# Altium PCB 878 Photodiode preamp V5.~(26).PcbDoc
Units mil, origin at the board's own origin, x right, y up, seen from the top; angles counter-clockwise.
Board outline 4488 x 4488 mil, 6 copper layers (Top Layer, Internal Plane 1, Dummy Ground, Dummy Power, Internal Plane 2, Bottom Layer), stack 21.034 mil thick; 182 components, 80 nets, 485 pads, 76 vias.
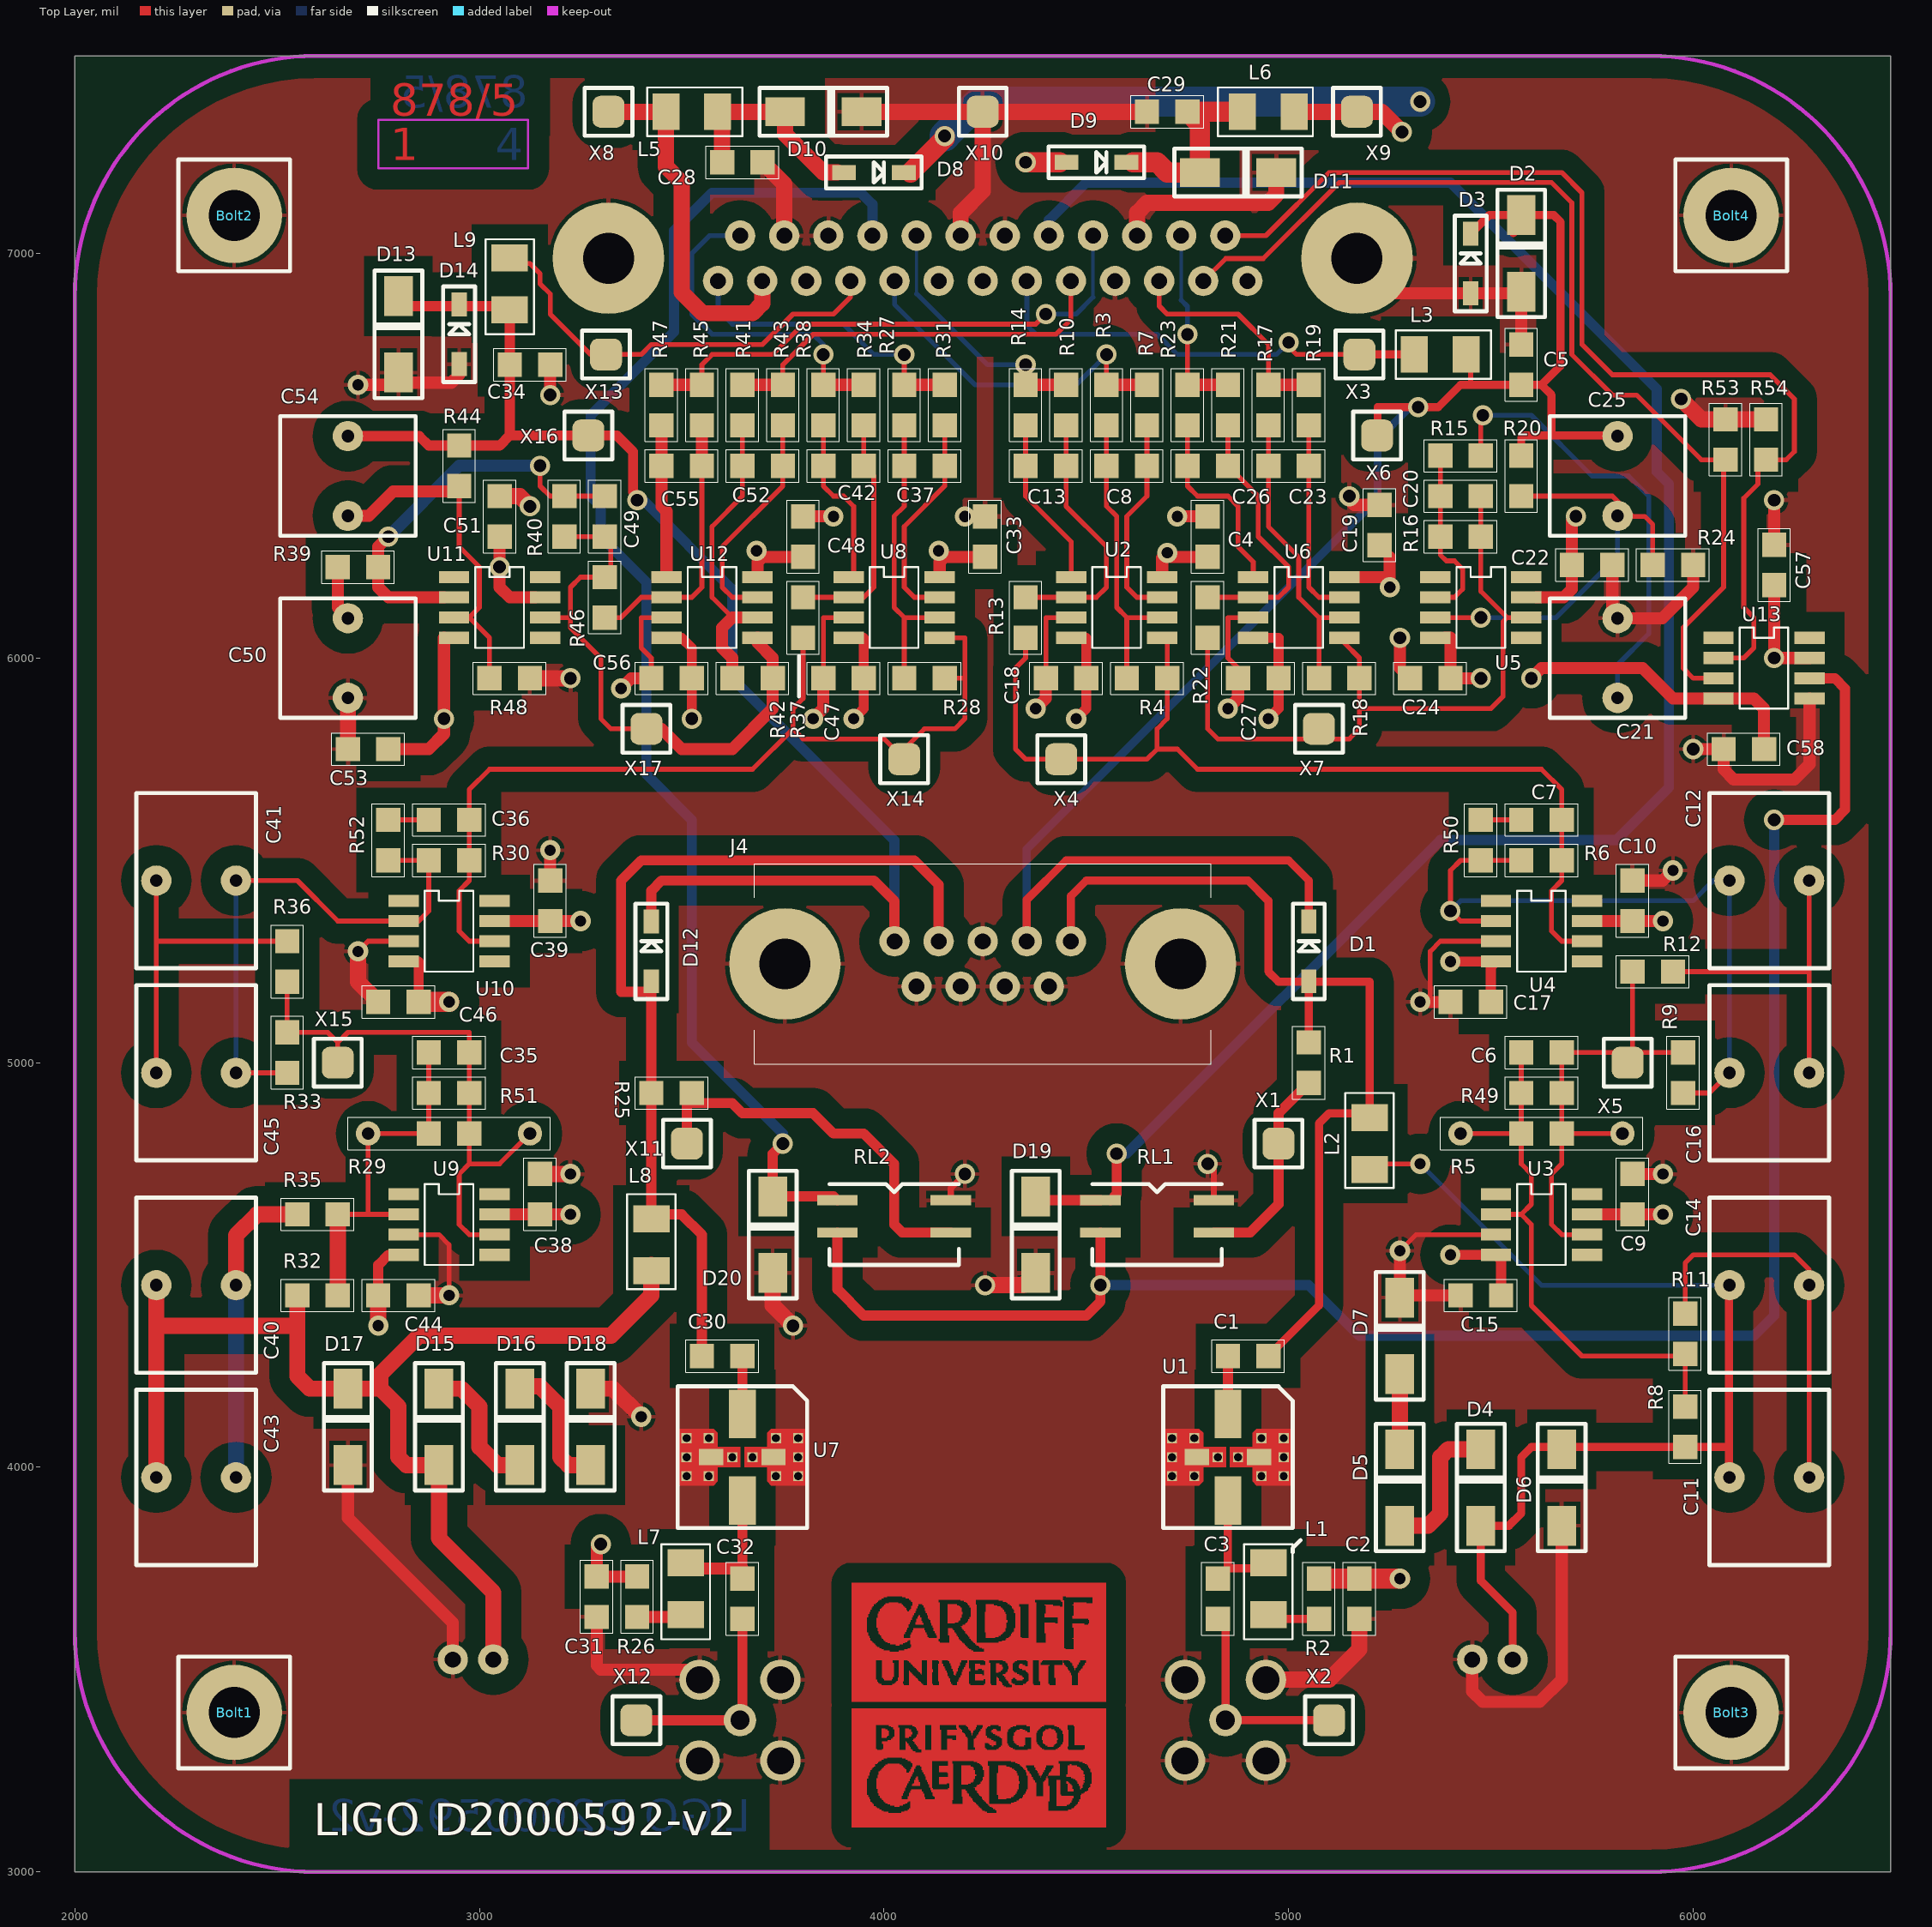
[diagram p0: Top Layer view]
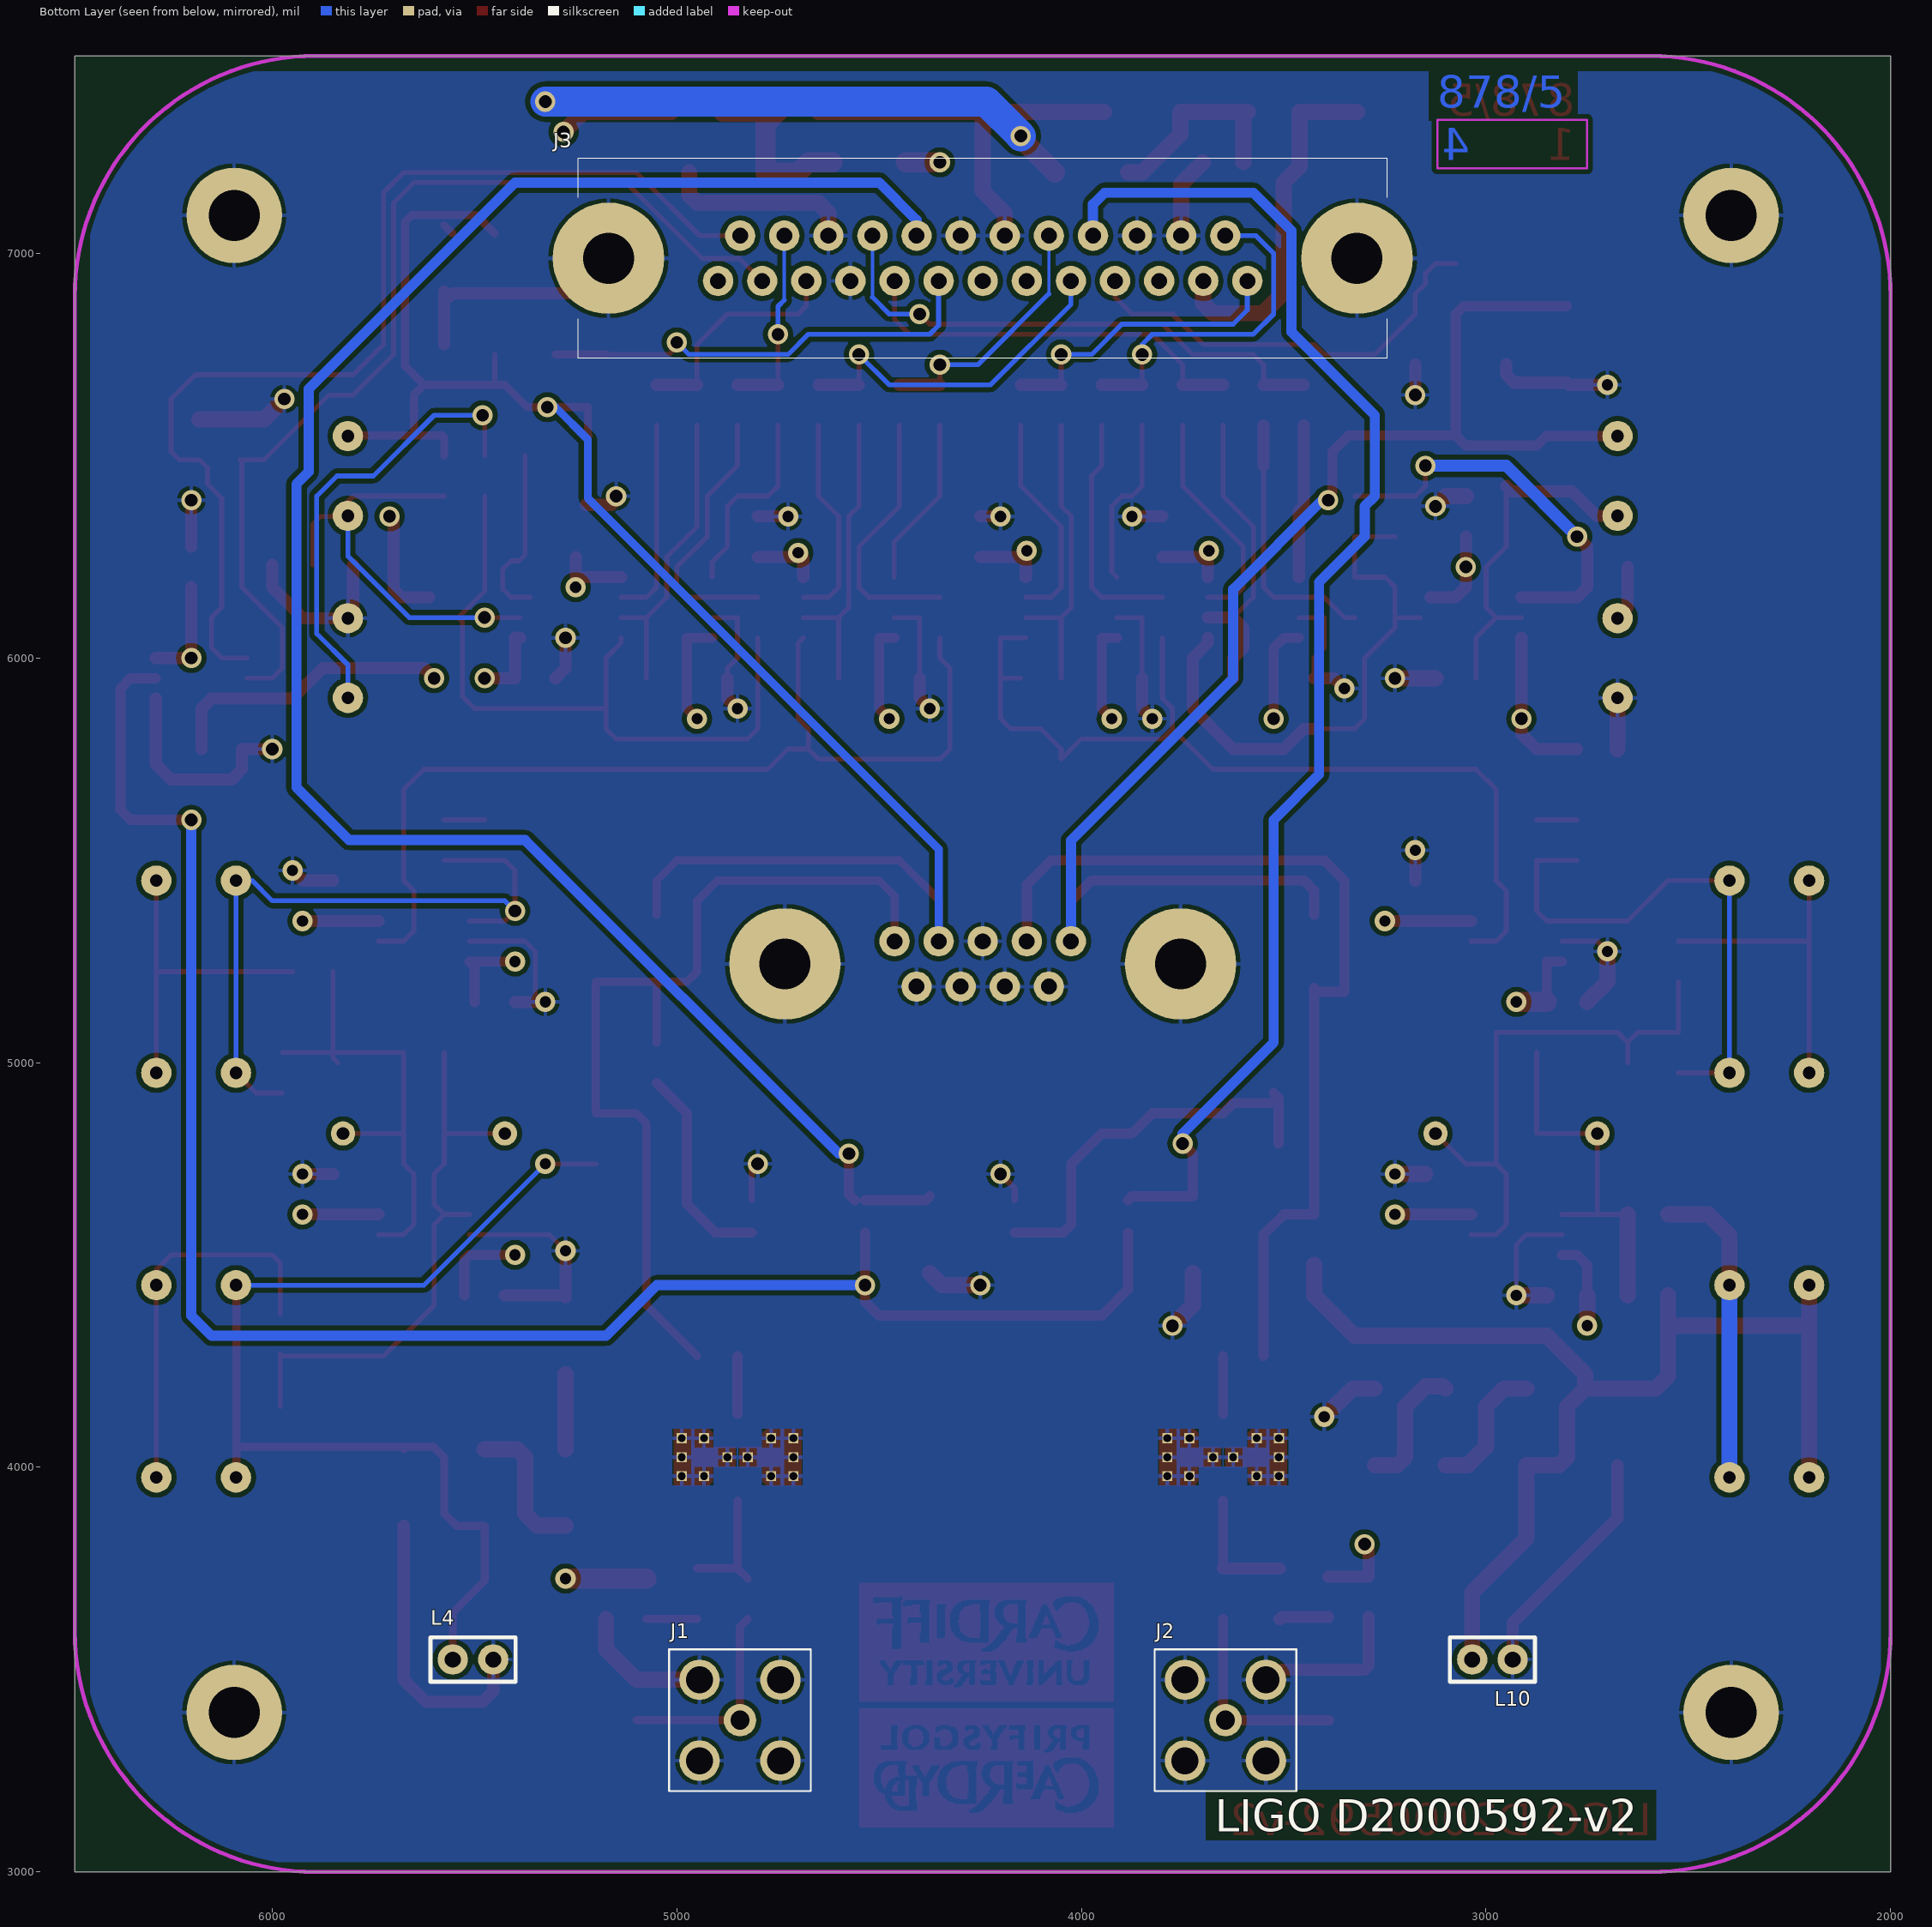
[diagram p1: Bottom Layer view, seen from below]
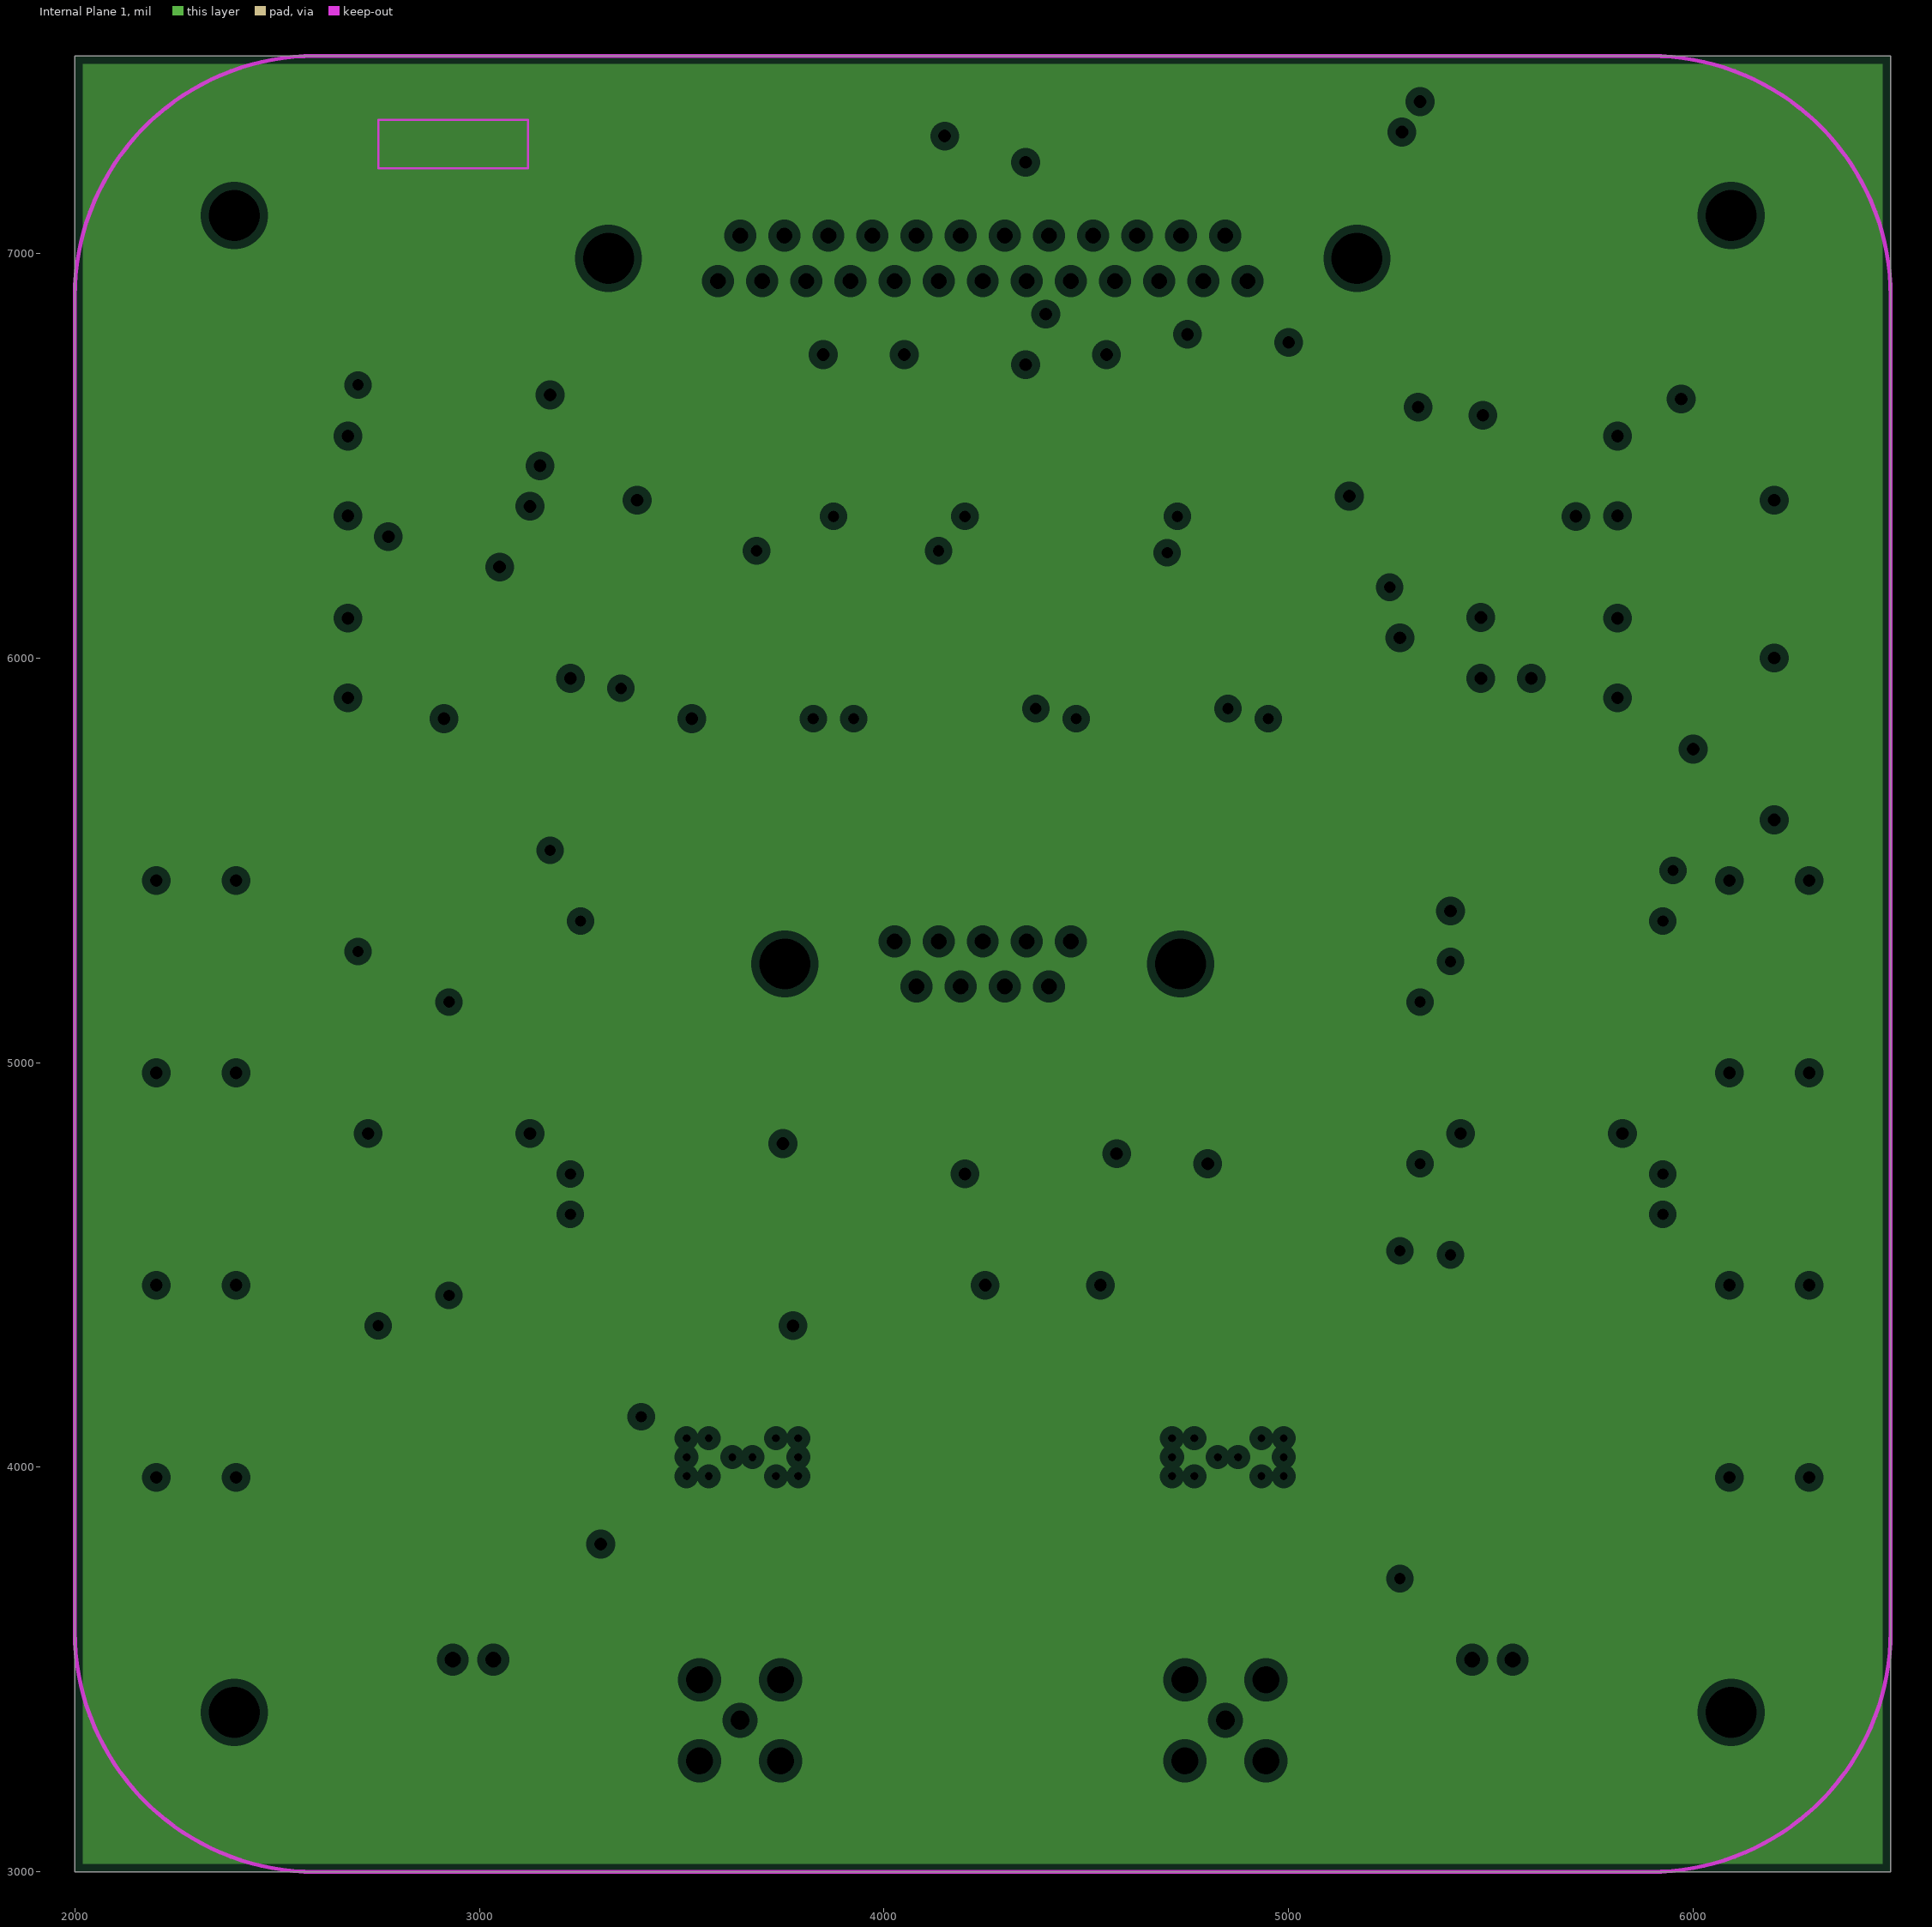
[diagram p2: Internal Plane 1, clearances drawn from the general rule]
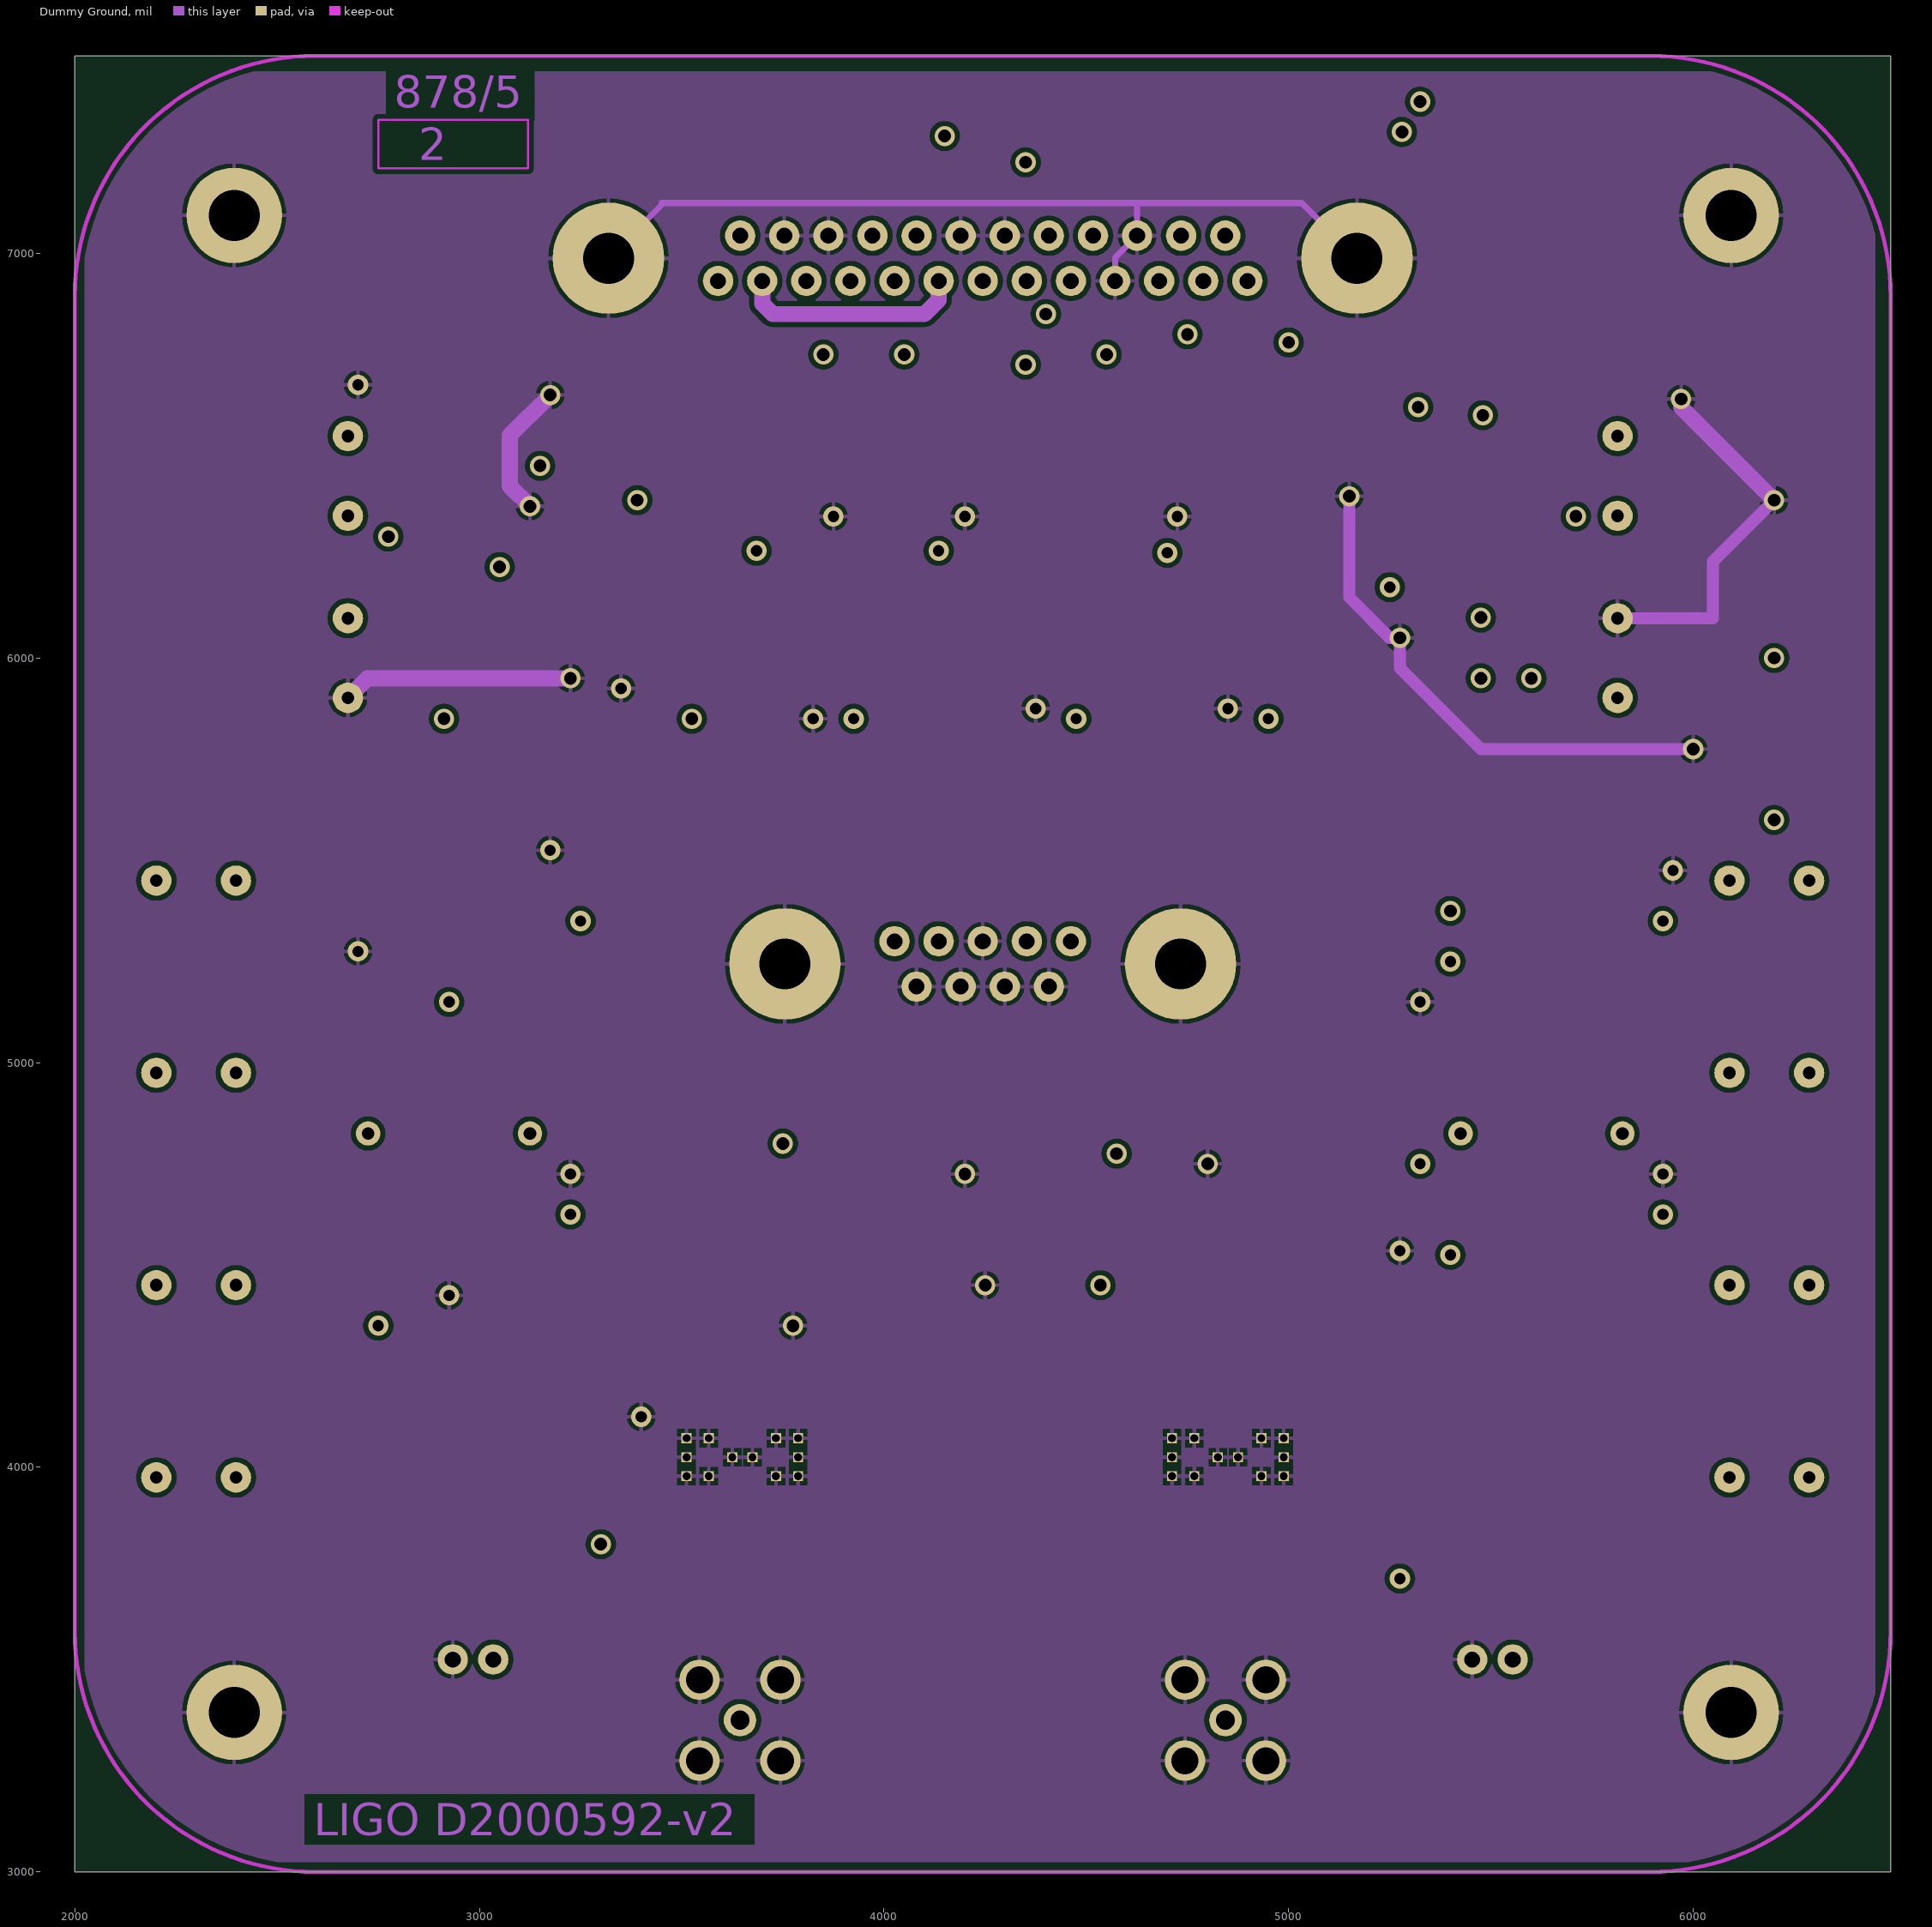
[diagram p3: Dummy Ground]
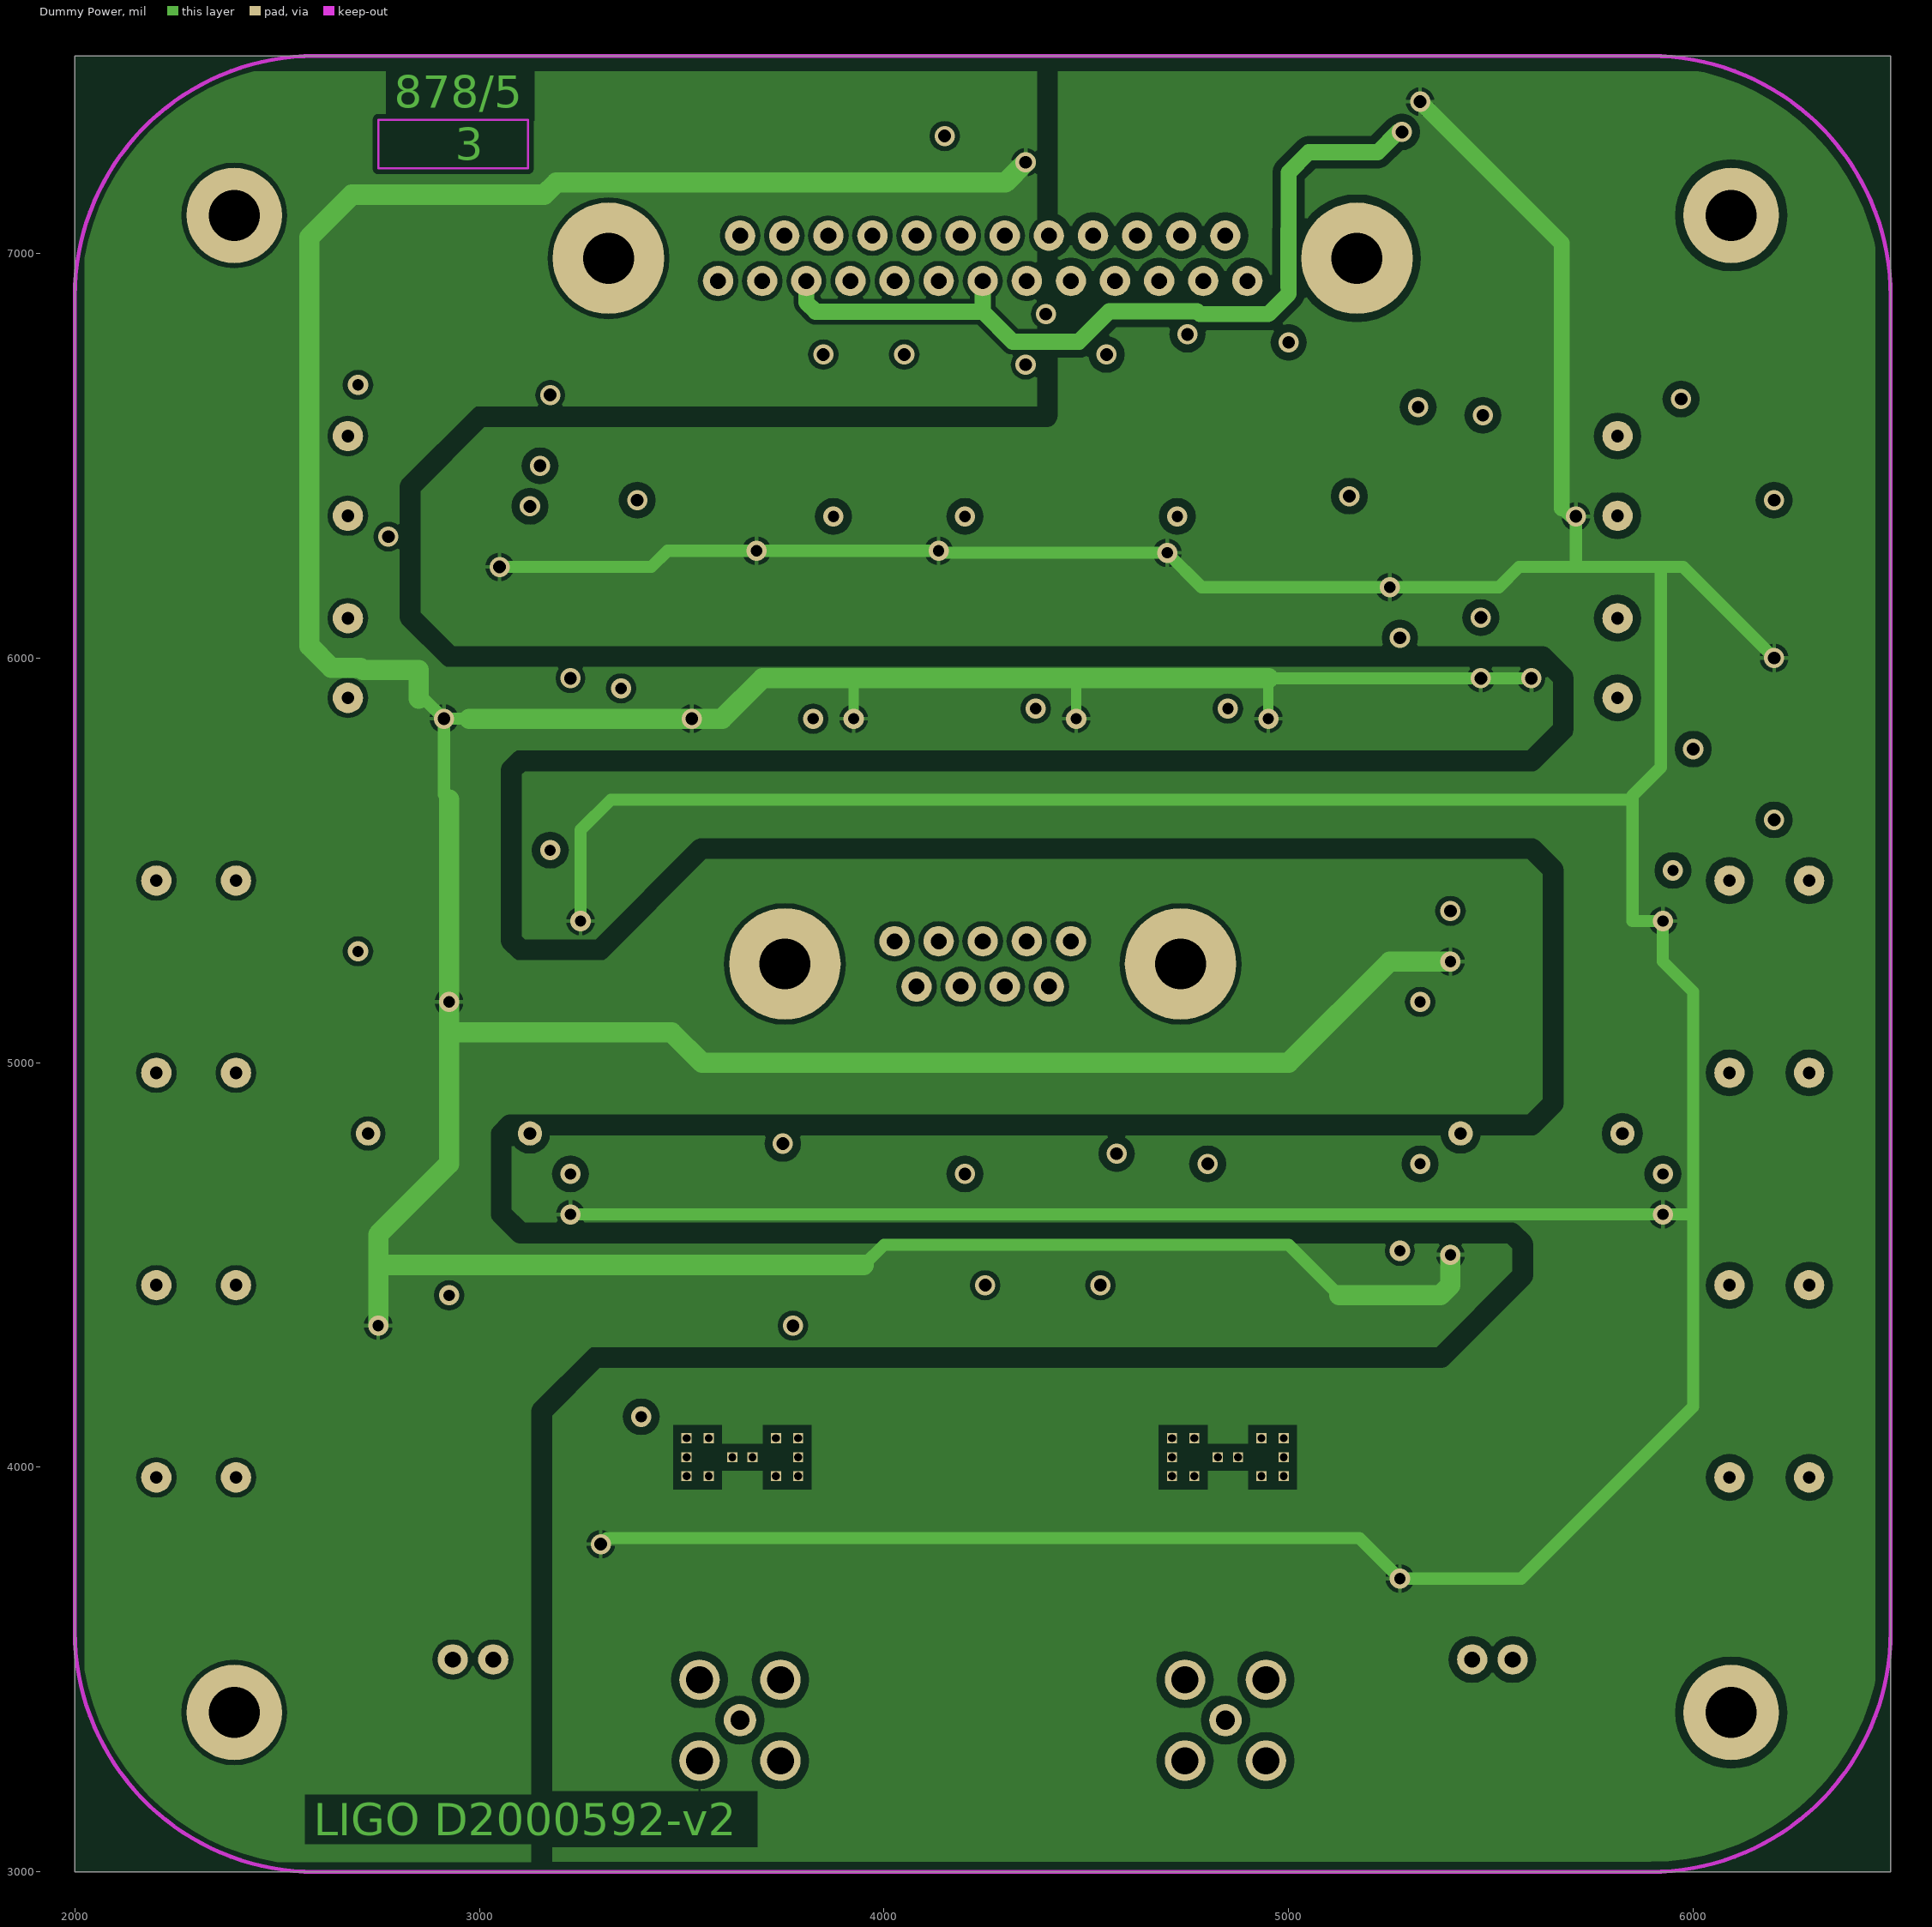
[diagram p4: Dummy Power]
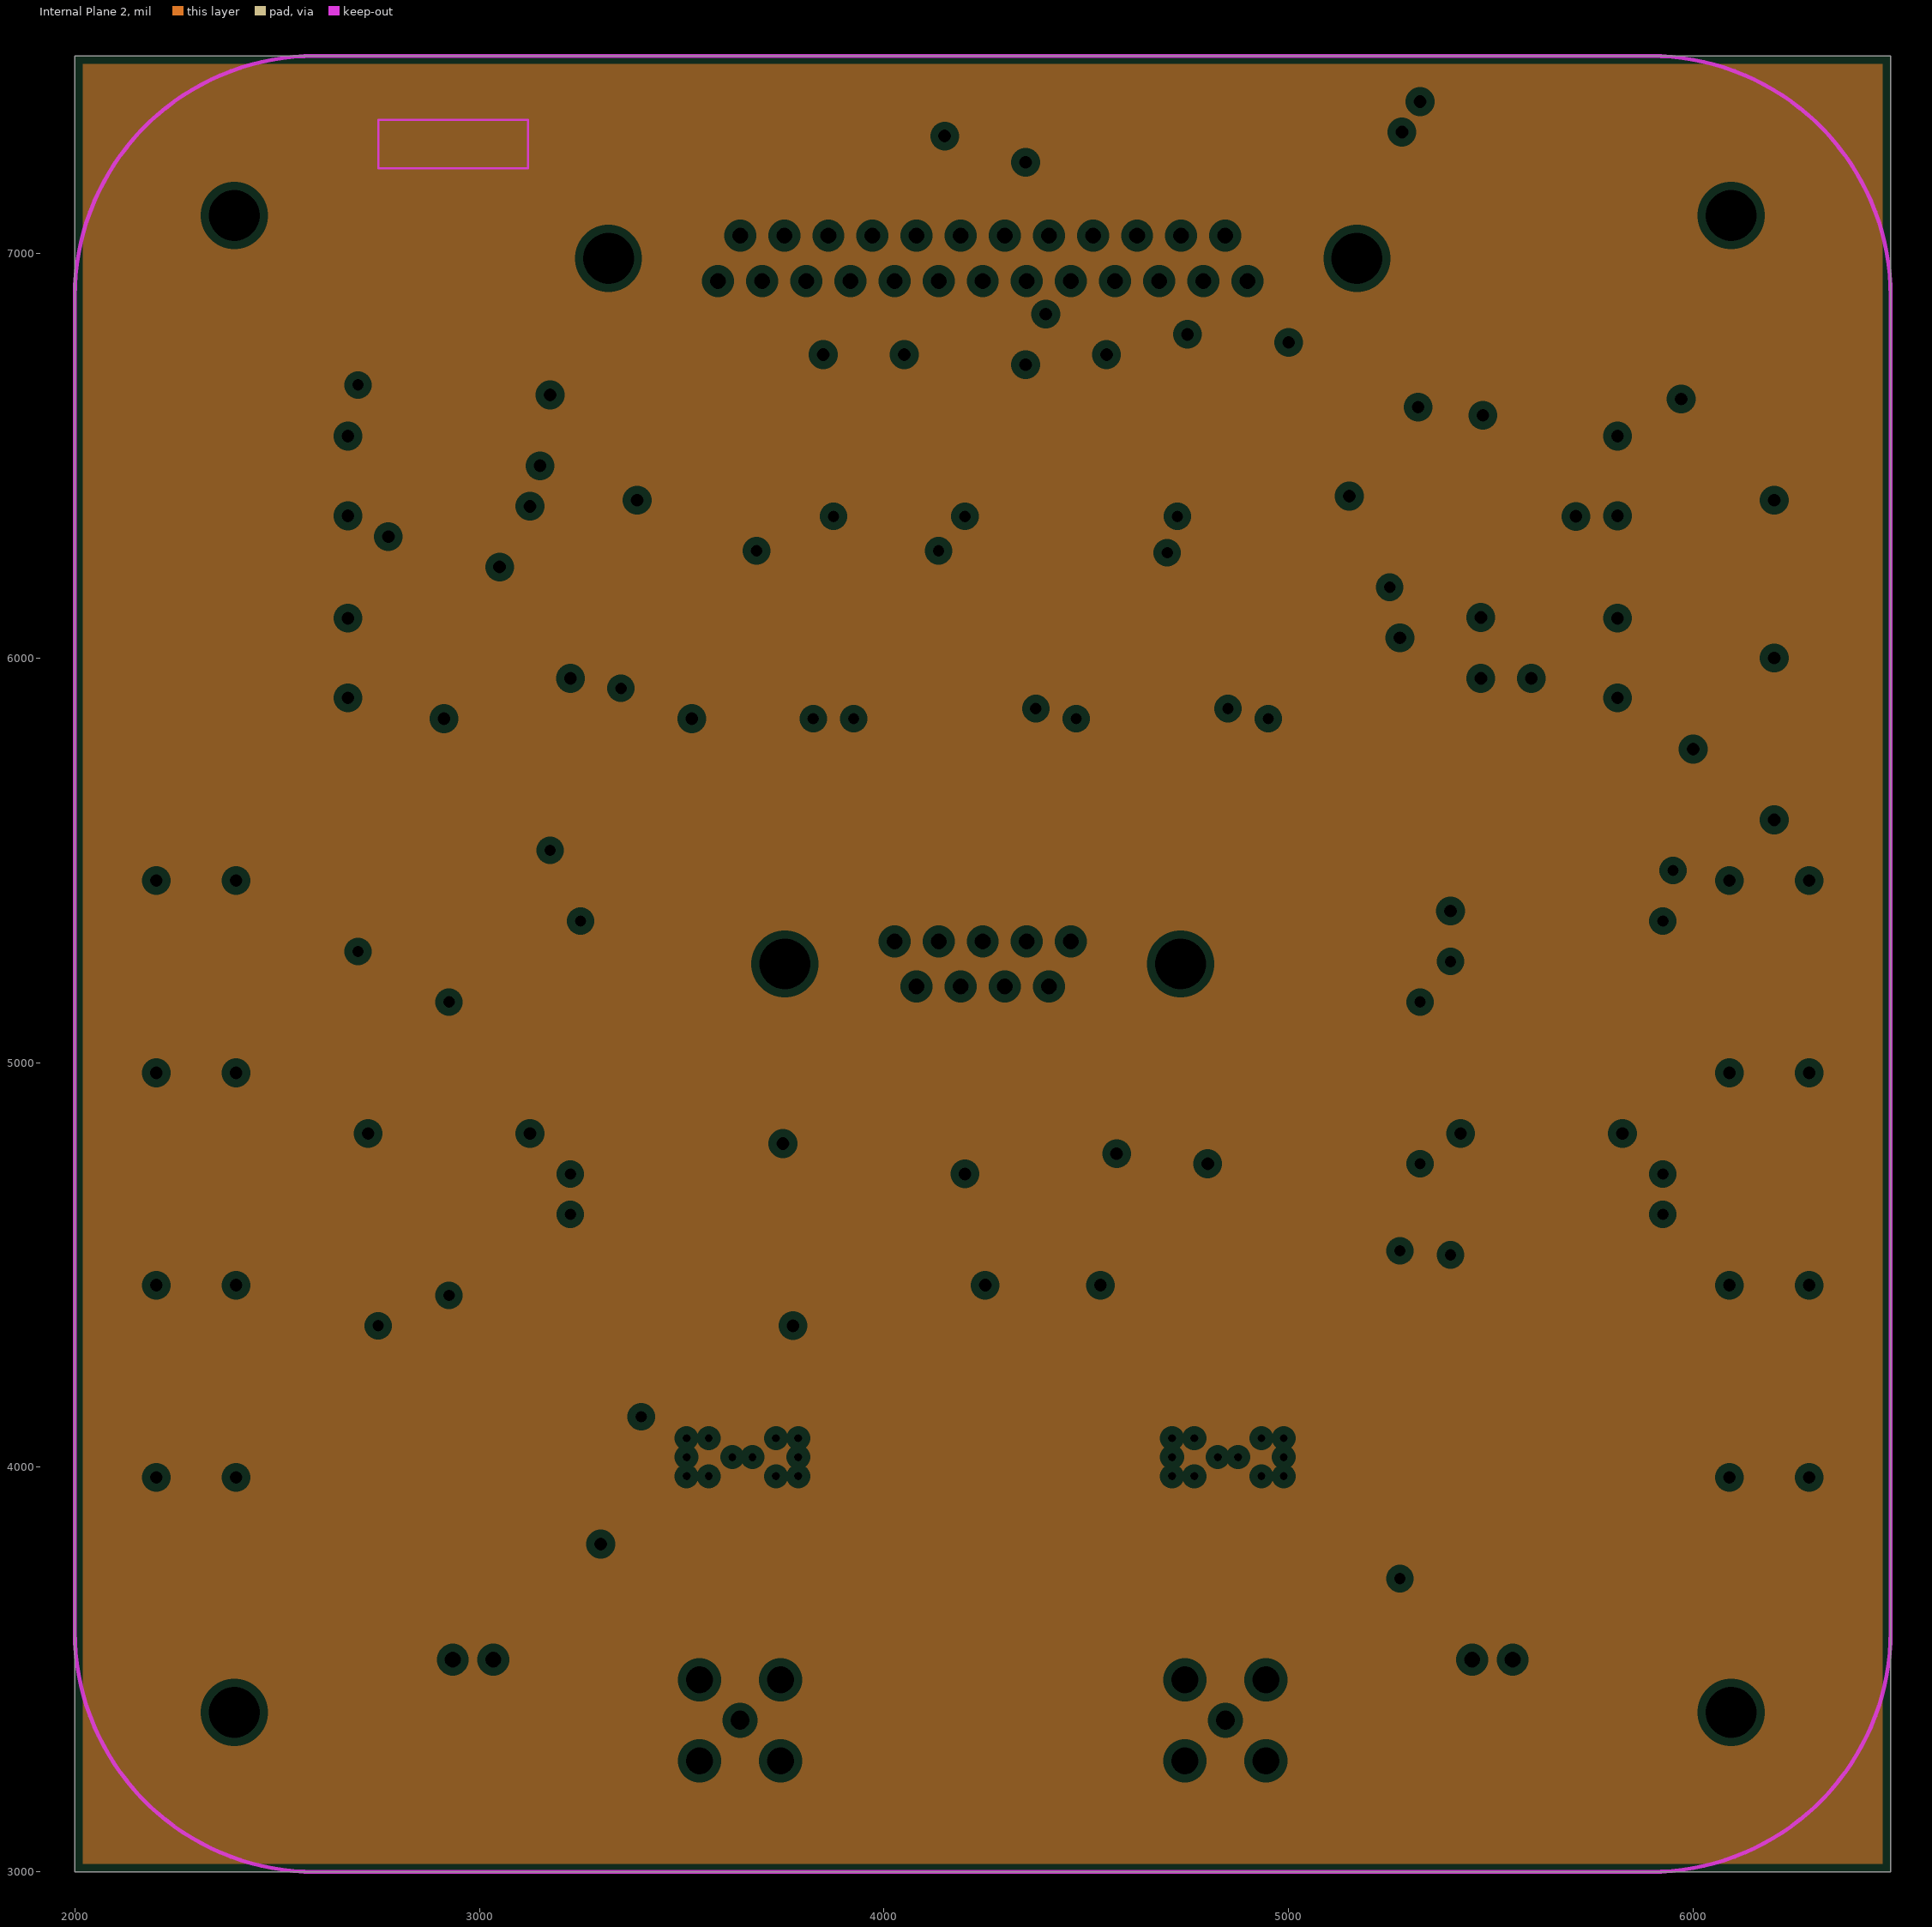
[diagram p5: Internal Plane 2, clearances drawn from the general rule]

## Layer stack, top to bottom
Top Solder: solder mask 0.4, Solder Resist, Dk 3.5
Top Layer: signal copper 1.4
Internal Plane 1: plane copper 1.4
Dummy Ground: signal copper 1.417
Dummy Power: signal copper 1.417
Internal Plane 2: plane copper 1.4
Dielectric 1: dielectric 12.6, FR-4, Dk 4.8
Bottom Layer: signal copper 1.4
Bottom Solder: solder mask 0.4, Solder Resist, Dk 3.5

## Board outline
2000,3000 6488,3000 6488,7488 2000,7488

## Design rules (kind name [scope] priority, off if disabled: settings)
Clearance Clearance_2 [InNamedPolygon('Top Layer-GND')] p1: gap=50
Clearance Clearance_1 [(InNamedPolygon('+15V_L04_P006'))] p2: gap=20
Clearance [All] p3: gap=12
HoleSize [All] p1: absolutevalues=TRUE maxlimit=150 minlimit=1 maxpercent=80.000 minpercent=20.000
PlaneClearance [All] p1: clearance=20
PlaneConnect [All] p1: planeconnectstyle=Relief reliefexpansion=20 reliefentries=4 reliefconductorwidth=10 reliefairgap=10
PolygonConnect [All] p1: connectstyle=Relief reliefconductorwidth=10 reliefentries=4 polygonreliefangle="90 Angle" airgapwidth=10
RoutingVias [All] p1: holewidth=31.5 width=50 viastyle="Through Hole" minholewidth=19.68 minwidth=30 maxholewidth=31.5 maxwidth=60
SilkToSilkClearance [All] p1: silktosilkclearance=5
SilkToSolderMaskClearance [IsPad] p1: minsilkscreentomaskgap=3 clearancetoexposedcopper=TRUE
SolderMaskExpansion [All] p1: expansion=4
Width [All] p1: maxlimit=200 minlimit=8 preferedwidth=12
25 further rules are at their usual default settings.

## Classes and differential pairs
component class "878 Photodiode preamp v5 P1": Bolt1 Bolt2 Bolt3 Bolt4 C1 C2 C3 C4 C5 C6 C7 C8 C9 C10 C11 C12 C13 C14 C15 C16 C17 C18 C19 C20 C21 C22 C23 C24 C25 C26 C27 C28 C29 C57 C58 D1 D2 D3 D4 D5 D6 D7 D8 D9 D10 D11 D19 J1 L1 L2 L3 L4 L5 L6 R1 R2 R3 R4 R5 R6 R7 R8 R9 R10 R11 R12 R13 R14 R15 R16 R17 R18 R19 R20 R21 R22 R23 R24 R49 R50 R53 R54 RL1 U1 U2 U3 U4 U5 U6 U13 X1 X2 X3 X4 X5 X6 X7 X8 X9 X10
component class "878 Photodiode preamp v5 P2": C30 C31 C32 C33 C34 C35 C36 C37 C38 C39 C40 C41 C42 C43 C44 C45 C46 C47 C48 C49 C50 C51 C52 C53 C54 C55 C56 D12 D13 D14 D15 D16 D17 D18 D20 J2 J3 J4 L7 L8 L9 L10 R25 R26 R27 R28 R29 R30 R31 R32 R33 R34 R35 R36 R37 R38 R39 R40 R41 R42 R43 R44 R45 R46 R47 R48 R51 R52 RL2 U7 U8 U9 U10 U11 U12 X11 X12 X13 X14 X15 X16 X17

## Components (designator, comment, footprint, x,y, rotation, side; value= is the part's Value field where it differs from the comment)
Bolt1 "Bolt M3" BOLT 2394,3394 r0 top
Bolt2 "Bolt M3" BOLT 2394,7094 r0 top
Bolt3 "Bolt M3" BOLT 6094,3394 r0 top
Bolt4 "Bolt M3" BOLT 6094,7094 r0 top
C1 "Cap200" HS0805Long 4900,4275 r180 top
C2 "Cap200" HS0805Long 5175,3675 r270 top
C3 "Cap200" HS0805Long 4825,3675 r270 top
C4 "Cap200" HS0805Long 4800,6300 r90 top
C5 "Cap200" HS0805Long 5575,6725 r90 top
C6 "Cap200" HS0805Long 5625,5025 r0 top
C7 "Cap200" HS0805Long 5625,5600 r0 top
C8 "Cap200" HS0805Long 4600,6475 r0 top
C9 "Cap200" HS0805Long 5850,4675 r90 top
C10 "Cap200" HS0805Long 5850,5400 r90 top
C11 "Cap200" "MKS2 7.2 11" 6188,3975 r0 top
C12 "Cap200" "MKS2 7.2 11" 6188,5450 r180 top
C13 "Cap200" HS0805Long 4400,6475 r180 top
C14 "Cap200" "MKS2 7.2 11" 6188,4450 r0 top
C15 "Cap200" HS0805Long 5475,4425 r180 top
C16 "Cap200" "MKS2 7.2 11" 6188,4975 r180 top
C17 "Cap200" HS0805Long 5450,5150 r180 top
C18 "Cap200" HS0805Long 4450,5950 r180 top
C19 "Cap200" HS0805Long 5225,6328.51 r90 top
C20 "Cap200" HS0805Long 5425,6400 r0 top
C21 "Cap200" "MKS2 7.2 8.5" 5813,6000 r270 top
C22 "Cap200" HS0805Long 5750,6230 r0 top
C23 "Cap200" HS0805Long 5000,6475 r0 top
C24 "Cap200" HS0805Long 5350,5950 r180 top
C25 "Cap200" "MKS2 7.2 8.5" 5813,6450 r270 top
C26 "Cap200" HS0805Long 4800,6475 r180 top
C27 "Cap200" HS0805Long 4925,5950 r180 top
C28 "Cap200" HS0805Long 3650,7225 r0 top
C29 "Cap200" HS0805Long 4700,7350 r180 top
C30 "Cap200" HS0805Long 3600,4275 r0 top
C31 "Cap200" HS0805Long 3290,3680 r270 top
C32 "Cap200" HS0805Long 3650,3675 r270 top
C33 "Cap200" HS0805Long 4250,6300 r90 top
C34 "Cap200" HS0805Long 3125,6725 r0 top
C35 "Cap200" HS0805Long 2925,5025 r0 top
C36 "Cap200" HS0805Long 2925,5600 r0 top
C37 "Cap200" HS0805Long 4100,6475 r0 top
C38 "Cap200" HS0805Long 3150,4675 r90 top
C39 "Cap200" HS0805Long 3175,5400 r90 top
C40 "Cap200" "MKS2 7.2 11" 2300,4450 r0 top
C41 "Cap200" "MKS2 7.2 11" 2300,5450 r0 top
C42 "Cap200" HS0805Long 3900,6475 r180 top
C43 "Cap200" "MKS2 7.2 11" 2300,3975 r0 top
C44 "Cap200" HS0805Long 2800,4425 r0 top
C45 "Cap200" "MKS2 7.2 11" 2300,4975 r0 top
C46 "Cap200" HS0805Long 2800,5150 r180 top
C47 "Cap200" HS0805Long 3900,5950 r180 top
C48 "Cap200" HS0805Long 3800,6300 r90 top
C49 "Cap200" HS0805Long 3310,6350 r270 top
C50 "Cap200" "MKS2 7.2 8.5" 2675,6000 r90 top
C51 "Cap200" HS0805Long 3050,6350 r90 top
C52 "Cap200" HS0805Long 3700,6475 r0 top
C53 "Cap200" HS0805Long 2725,5775 r180 top
C54 "Cap200" "MKS2 7.2 8.5" 2675,6450 r270 top
C55 "Cap200" HS0805Long 3500,6475 r180 top
C56 "Cap200" HS0805Long 3475,5950 r180 top
C57 "Cap200" HS0805Long 6200,6230 r270 top
C58 "Cap200" HS0805Long 6125,5775 r180 top
D1 "60V 1A" SOD123 5050,5275 r270 top
D2 "SMAJxxCA" DO214AC 5575,7000 r270 top
D3 "60V 1A" SOD123 5450,6975 r270 top
D4 "1N4007" DO214AC 5475,3950 r270 top
D5 "1N4007" DO214AC 5275,3950 r270 top
D6 "1N4007" DO214AC 5675,3950 r270 top
D7 "1N4007" DO214AC 5275,4325 r270 top
D8 "60V 1A" SOD123 3975,7200 r180 top
D9 "60V 1A" SOD123 4525,7225 r180 top
D10 "SMAJxxCA" DO214AC 3850,7350 r180 top
D11 "SMAJxxCA" DO214AC 4875,7200 r180 top
D12 "60V 1A" SOD123 3425,5275 r270 top
D13 "SMAJxxCA" DO214AC 2800,6800 r270 top
D14 "60V 1A" SOD123 2950,6800 r270 top
D15 "1N4007" DO214AC 2900,4100 r270 top
D16 "1N4007" DO214AC 3100,4100 r270 top
D17 "1N4007" DO214AC 2675,4100 r270 top
D18 "1N4007" DO214AC 3275,4100 r270 top
D19 "1N4004" DO214AC 4375,4575 r270 top
D20 "1N4004" DO214AC 3725,4575 r270 top
J1 "SMA" "PCB SMB" 4844,3375 r180 bottom
J2 "SMA" "PCB SMB" 3644,3375 r180 bottom
J3 "D connector 25 way" "D Socket Straight PCB 25 Way" 4244,6987.81 r0 bottom
J4 "D connector 9 way" "D Plug Straight PCB 9 Way" 4244,5244 r0 top
L1 "Inductor" HS1210 4950,3700 r270 top
L2 "Inductor" HS1210 5200,4800 r90 top
L3 "Inductor" HS1210 5375,6750 r0 top
L4 "Inductor" "2 way 0.1\"" 5503.75,3525 r0 bottom
L5 "Inductor" HS1210 3525,7350 r0 top
L6 "Inductor" HS1210 4950,7350 r180 top
L7 "Inductor" HS1210 3510,3700 r270 top
L8 "Inductor" HS1210 3425,4550 r90 top
L9 "Inductor" HS1210 3075,6925 r270 top
L10 "Inductor" "2 way 0.1\"" 2984.25,3525 r0 bottom
R1 "Res" hs0805long 5050,5000 r90 top
R2 "Res" hs0805long 5075,3675 r90 top
R3 "Res" hs0805long 4550,6625 r90 top
R4 "Res" hs0805long 4650,5950 r180 top
R5 "Res" SpecialR 5625,4825 r0 top
R6 "Res" hs0805long 5625,5500 r0 top
R7 "Res" hs0805long 4650,6625 r90 top
R8 "Res" hs0805long 5980,4100 r90 top
R9 "Res" hs0805long 5975,4975 r270 top
R10 "Res" hs0805long 4450,6625 r90 top
R11 "Res" hs0805long 5980,4330 r270 top
R12 "Res" hs0805long 5900,5225 r0 top
R13 "Res" hs0805long 4350,6100 r90 top
R14 "Res" hs0805long 4350,6625 r90 top
R15 "Res" hs0805long 5425,6500 r0 top
R16 "Res" hs0805long 5425,6300 r0 top
R17 "Res" hs0805long 4950,6625 r90 top
R18 "Res" hs0805long 5125,5950 r180 top
R19 "Res" hs0805long 5050,6625 r90 top
R20 "Res" hs0805long 5575,6450 r90 top
R21 "Res" hs0805long 4850,6625 r90 top
R22 "Res" hs0805long 4800,6100 r90 top
R23 "Res" hs0805long 4750,6625 r90 top
R24 "Res" hs0805long 5950,6230 r180 top
R25 "Res" hs0805long 3475,4925 r180 top
R26 "Res" hs0805long 3390,3680 r90 top
R27 "Res" hs0805long 4050,6625 r90 top
R28 "Res" hs0805long 4100,5950 r180 top
R29 "Res" SpecialR 2925,4825 r0 top
R30 "Res" hs0805long 2925,5500 r0 top
R31 "Res" hs0805long 4150,6625 r90 top
R32 "Res" hs0805long 2600,4425 r0 top
R33 "Res" hs0805long 2525,5025 r270 top
R34 "Res" hs0805long 3950,6625 r90 top
R35 "Res" hs0805long 2600,4625 r0 top
R36 "Res" hs0805long 2525,5250 r90 top
R37 "Res" hs0805long 3800,6100 r90 top
R38 "Res" hs0805long 3850,6625 r90 top
R39 "Res" hs0805long 2700,6225 r180 top
R40 "Res" hs0805long 3210,6350 r270 top
R41 "Res" hs0805long 3650,6625 r90 top
R42 "Res" hs0805long 3675,5950 r180 top
R43 "Res" hs0805long 3750,6625 r90 top
R44 "Res" hs0805long 2950,6475 r90 top
R45 "Res" hs0805long 3550,6625 r90 top
R46 "Res" hs0805long 3310,6150 r270 top
R47 "Res" hs0805long 3450,6625 r90 top
R48 "Res" hs0805long 3075,5950 r180 top
R49 "Res" hs0805long 5625,4925 r0 top
R50 "Res" hs0805long 5475,5550 r90 top
R51 "Res" hs0805long 2925,4925 r0 top
R52 "Res" hs0805long 2775,5550 r90 top
R53 "Res" HS0805Long 6080,6540 r270 top
R54 "Res" HS0805Long 6180,6540 r270 top
RL1 "9901 relay" "9901 Relay" 4675,4600 r0 top
RL2 "9901 relay" "9901 Relay" 4025,4600 r0 top
U1 "MAR-6SM" ww107 4850,4025 r180 top
U2 "AD8672ARZ" "SOIC 8" 4575,6125 r270 top
U3 "LT1028" "SOIC 8" 5625,4600 r270 top
U4 "LT1028" "SOIC 8" 5625,5325 r270 top
U5 "LT1028" "SOIC 8" 5475,6125 r270 top
U6 "AD8672ARZ" "SOIC 8" 5025,6125 r270 top
U7 "MAR-6SM" ww107 3650,4025 r180 top
U8 "AD8672ARZ" "SOIC 8" 4025,6125 r270 top
U9 "LT1028" "SOIC 8" 2925,4600 r270 top
U10 "LT1028" "SOIC 8" 2925,5325 r270 top
U11 "LT1028" "SOIC 8" 3050,6125 r270 top
U12 "AD8672ARZ" "SOIC 8" 3575,6125 r270 top
U13 "AD620" "SOIC 8" 6175,5975 r270 top
X1 "TestPoint" "SM Test point" 4975,4800 r0 top
X2 "TestPoint" "SM Test point" 5100,3375 r0 top
X3 "TestPoint" "SM Test point" 5175,6750 r90 top
X4 "TestPoint" "SM Test point" 4438,5750 r90 top
X5 "TestPoint" "SM Test point" 5838,5000 r90 top
X6 "TestPoint" "SM Test point" 5218.68,6550 r0 top
X7 "TestPoint" "SM Test point" 5075,5825 r0 top
X8 "TestPoint" "SM Test point" 3319,7350 r0 top
X9 "TestPoint" "SM Test point" 5169,7350 r0 top
X10 "TestPoint" "SM Test point" 4244,7350 r0 top
X11 "TestPoint" "SM Test point" 3513,4800 r0 top
X12 "TestPoint" "SM Test point" 3388,3375 r0 top
X13 "TestPoint" "SM Test point" 3313,6750 r0 top
X14 "TestPoint" "SM Test point" 4050,5750 r90 top
X15 "TestPoint" "SM Test point" 2650,5000 r90 top
X16 "TestPoint" "SM Test point" 3269.32,6550 r0 top
X17 "TestPoint" "SM Test point" 3413,5825 r0 top

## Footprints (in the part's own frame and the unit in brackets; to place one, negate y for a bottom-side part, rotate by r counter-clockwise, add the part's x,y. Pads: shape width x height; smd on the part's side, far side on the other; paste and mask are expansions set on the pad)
"2 way 0.1\"" [mm] "two wire component!"
  round 1.905 hole 1: 1(-1.27,0) 2(1.27,0)
  silkscreen extent -2.67,-1.4 2.67,1.4
"9901 Relay" [mil] "SM reed relay"
  rect 100x25 smd: 1(-140,60) 2(140,60) 5(-140,-20) 6(140,-20)
  silkscreen extent -160,-100 160,100
BOLT [mm] "M3 mounting bolt"
  round 6 hole 3.2: 1(0,0)
  silkscreen extent -3.5,-3.5 3.5,3.5
"D Plug Straight PCB 9 Way" [mil] "D Plug Straight PCB 9 Way"
  round 75 hole 39.37: 1(-218,56) 2(-109,56) 3(0,56) 4(109,56) 5(218,56) 6(-163.5,-56) 7(-54.5,-56) 8(54.5,-56) 9(163.5,-56)
  round 275.59 hole 125.98: 10(-489,0) 10(489,0)
  silkscreen extent -564,-247 564,247
"D Socket Straight PCB 25 Way" [mil] "D socket Straight PCB 25 Way"
  round 75 hole 39.37: 1(654,56) 2(545,56) 3(436,56) 4(327,56) 5(218,56) 6(109,56) 7(0,56) 8(-109,56) 9(-218,56) 10(-327,56) 11(-436,56) 12(-545,56) 13(-654,56) 14(599.5,-56) 15(490.5,-56) 16(381.5,-56) 17(272.5,-56) 18(163.5,-56) 19(54.5,-56) 20(-54.5,-56) 21(-163.5,-56) 22(-272.5,-56) 23(-381.5,-56) 24(-490.5,-56) 25(-599.5,-56)
  round 275.59 hole 125.98: 26(-925,0) 26(925,0)
  silkscreen extent -1000,-247 1000,247
DO214AC [mm] "DO214AC"
  rect 2.5x1.8 smd: 1(-2.4,0) 2(2.4,0)
  silkscreen extent -4,-1.5 4,1.5
HS0805Long [mil] "0805 on big pads for hand soldering will also take 1206"
  rect 60x60 smd: 1(-50,0) 2(50,0)
  silkscreen extent -90,-40 90,40
hs0805long [mil] "0805 on big pads for hand soldering will also take 1206"
  rect 60x60 smd: 1(-50,0) 2(50,0)
  silkscreen extent -90,-40 90,40
HS1210 [mm] "Tant case B (A will also fit!)"
  rect 1.7x2.286 smd: 1(-1.625,0) 2(1.626,0)
  silkscreen extent -2.79,-1.52 3.18,1.52
"MKS2 7.2 8.5" [mm] "MKS2 7.2 by 8.5"
  round 1.905 hole 0.8: 1(-2.5,0) 2(2.5,0)
  silkscreen extent -3.75,-4.25 3.75,4.25
"MKS2 7.2 11" [mm] "MKS2 7.2 by 11 by 16"
  round 1.905 hole 0.8: 1(-2.5,0) 2(2.5,0)
  silkscreen extent -3.75,-5.5 3.75,5.5
"PCB SMB" [mm] "PCB mount SMB connector"
  round 2.032 hole 1.2: 1(0,0)
  round 2.54 hole 1.7: 2(-2.54,-2.54) 2(-2.54,2.54) 2(2.54,-2.54) 2(2.54,2.54)
  silkscreen extent -4.45,-4.45 4.45,4.45
"SM Test point" [mm] "SM Test point 100 x 100mil"
  rrect50% 2x2 smd: 1(0,0)
  silkscreen extent -1.5,-1.5 1.5,1.5
SOD123 [mm] "SOD123 Diode (500mW Zener etc)"
  rect 1.5x0.95 smd: 1(-1.875,0) 2(1.875,0)
  silkscreen extent -3,-1 3,1
"SOIC 8" [mil] "SOIC 8"
  rect 30x75 smd: 1(-75,-112.5) 2(-25,-112.5) 3(25,-112.5) 4(75,-112.5) 5(75,112.5) 6(25,112.5) 7(-25,112.5) 8(-75,112.5)
  silkscreen extent -100,-60 100,60
SpecialR [mil] "SM or TH"
  round 60 hole 31.5: 1(-200,0) 2(200,0)
  rect 60x60 smd: 1(-50,0) 2(50,0)
  silkscreen extent -250,-40 250,40
ww107 [mil] "Mini circuits MAR-6SM"
  rect 66x120 smd: 1(0,-107) 3(0,107)
  rect 25x25 hole 19.68: 2(25,0) 2(83,-47) 2(83,47) 2(138,-47) 2(138,0) 2(138,47) 4(-138,-47) 4(-138,0) 4(-138,47) 4(-83,-47) 4(-83,47) 4(-25,0)
  rect 60x40 smd: 2(77,0) 4(-77,0)
  Top Layer region: 158,70 158,-70 71,-70 61,-60 61,-25 5,-25 5,25 61,25 61,60 71,70
  Top Layer region: -158,70 -158,-70 -71,-70 -61,-60 -61,-25 -5,-25 -5,25 -61,25 -61,60 -71,70
  silkscreen extent -160,-175 160,175

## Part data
C1 C2 C3 C4 C5 C6 C7 C8 C9 C10 C11 C12 C13 C14 C15 C16 C17 C18 C19 C20 C21 C22 C23 C24 C25 C26 C27 C28 C29 C30 C31 C32 C33 C34 C35 C36 C37 C38 C39 C40 C41 C42 C43 C44 C45 C46 C47 C48 C49 C50 C51 C52 C53 C54 C55 C56 C57 C58: "Cap 0.2\" pitch"
D1 D3 D8 D9 D12 D14: library part "Sckottky Diode"
D2 D10 D11 D13: "TVS"
D4 D5 D6 D7 D15 D16 D17 D18: library part 1N4004
J1 J2: library part "PCB SMB"
U2 U6 U8 U12: library part DualOpAmp
U3 U4 U5 U9 U10 U11: library part SingleOpAmp

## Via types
v1: diameter 50, hole 31.5, Top Layer to Bottom Layer, 42 vias
v2: diameter 50, hole 28, Top Layer to Bottom Layer, 34 vias

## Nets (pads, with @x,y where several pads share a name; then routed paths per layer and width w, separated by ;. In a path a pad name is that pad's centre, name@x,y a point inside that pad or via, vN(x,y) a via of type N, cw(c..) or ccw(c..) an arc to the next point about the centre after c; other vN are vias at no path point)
+15V: C2.1 C4.1 C9.1 C10.1 C19.1 C22.1 C31.1 C33.1 C38.1 C39.1 C48.1 C51.1 C57.2 D8.1 R2.2 R26.2 U2.8 U3.7 U4.7 U5.7 U6.8 U8.8 U9.7 U10.7 U11.7 U12.8 U13.7 | length 19333.5
  Top Layer w30: U9.7 C38.1 v2(3225,4625) ; U10.7 C39.1 v2(3250,5350) ; C51.1 v1(3050,6225) 3050,6175 3075,6150 U11.7@3137.5,6150 ; v1(3300,3810) 3290,3810 C31.1 R26.2 ; U12.8 3687.5,6237.5 3700,6250 C48.1 ; U8.8 4137.5,6237.5 4150,6250 C33.1 ; U2.8 4687.5,6247.5 v2(4700,6260) 4710,6250 C4.1 ; U6.8 5250,6200 ; v2(5250,6175) 5250,6200 ; C19.1@5250,6250 5250,6200 ; U5.7@5612.5,6150 5680,6150 5700,6170 C22.1 5700,6340 v1(5710,6350) ; U3.7 C9.1 v2(5925,4625) ; U4.7 C10.1 v2(5925,5350) ; C57.2@6200,6175 v1(6200,6000) U13.7
  Top Layer w50: D8.1@4065.55,7200 4150,7284.45 v1(4150,7290) ; R2.2 C2.1 v2(5275,3725)
  Dummy Power w30: v1(3050,6225) 3425,6225 3465,6265 v2(3685,6265) v2(4135,6265) 4140,6260 v2(4700,6260) 4785,6175 v2(5250,6175) 5520,6175 5570,6225 5710,6225 ; v2(3225,4625) v2(5925,4625) 6000,4625 ; v2(3250,5350) 3250,5575 3325,5650 5850,5650 ; v1(3300,3810) 3315,3825 5175,3825 v2(5275,3725) 5575,3725 6000,4150 6000,4625 ; 5675,6370 5695,6350 v1(5710,6350) 5710,6225 ; v1(6200,6000) 5975,6225 5920,6225 ; 5710,6225 5920,6225 ; 5850,5650 5850,5350 v2(5925,5350) 5925,5250 6000,5175 6000,4625 ; 5850,5650 5850,5660 5920,5730 5920,6225
  Dummy Power w40: v1(5325,7375) 5675,7025 5675,6370
  Bottom Layer w75: v1(4150,7290) 4235,7375 v1(5325,7375)
+15VIN: J3.8 J3.12 L5.1 X8.1 | length 1454.3
  Top Layer w40: X8.1 L5.1 3461.02,7213.98 3500,7175 3500,6904 3552,6852 3675,6852 3699,6876 J3.12
  Dummy Ground w40: J3.12 3699,6876 3725,6850 4100,6850 4135,6885 J3.8
-15V: C15.1 C17.1 C18.1 C24.1 C27.1 C44.1 C46.1 C47.1 C53.1 C56.1 C58.1 D9.2 U2.4 U3.4 U4.4 U5.4 U6.4 U8.4 U9.4 U10.4 U11.4 U12.4 U13.4 | length 16605.1
  Top Layer w25: C44.1 2750,4500 2775,4525 U9.4 ; U10.4 2850,5250 C46.1 ; U12.4 3500,6050 3525,6025 C56.1 v1(3525,5850) ; U8.4 3950,6050 C47.1 3950,5875 v2(3925,5850) ; U2.4 4500,6050 C18.1 4500,5875 v2(4475,5850) ; U6.4 4975,6050 C27.1 4975,5875 v2(4950,5850) ; v2(5400,4525) U3.4 5525,4512.5 C15.1 ; v2(5400,5250) U4.4 5500,5237.5 C17.1
  Top Layer w30: C53.1 2875,5775 2912.5,5812.5 v1(2912.5,5850) U11.4@2912.5,6050 ; U5.4@5387.5,6050 5400,6050 C24.1 v1(5475,5950) ; v1(5600,5950) 5625,5975 5875,5975 5950,5900 U13.4 6150,5900 6175,5875 C58.1
  Top Layer w40: v2(2750,4350) C44.1
  Top Layer w50: C46.1 v2(2925,5150) ; v1(4350,7225) D9.2@4434.45,7225
  Dummy Power w25: v2(3925,5850) 3925,5950 ; v2(4475,5850) 4475,5950 ; v2(4950,5850) 4950,5950
  Dummy Power w30: 2850,5900 2862.5,5900 v1(2912.5,5850) ; 2925,5650 2912.5,5662.5 v1(2912.5,5850) ; 2975,5850 v1(2912.5,5850) ; 3950,4500 4000,4550 5000,4550 5125,4425 ; 4950,5950 v1(5475,5950) v1(5600,5950)
  Dummy Power w50: v2(2750,4350) 2750,4500 ; 2850,5900 2850,5970 2711.93,5970 2705.86,5976.07 2633.93,5976.07 2580,6030 2580,7040 2685,7145 3160,7145 3190,7175 4300,7175 v1(4350,7225) ; 2925,5650 v2(2925,5150) 2925,5075 ; 2975,5850 v1(3525,5850) 3600,5850 3700,5950 3925,5950 4475,5950 4950,5950 ; 3950,4500 2750,4500 ; 5125,4425 5375,4425 5400,4450 v2(5400,4525) ; v2(5400,5250) 5250,5250 5000,5000 3550,5000 3475,5075 2925,5075 ; 2750,4500 2750,4575 2925,4750 2925,5075
-15VIN: J3.7 J3.11 L6.1 X9.1 | length 2324.3
  Top Layer w40: L6.1 X9.1 5230,7350 v1(5280,7300)
  Dummy Power w40: J3.11 3808,6879 3831,6856 4244,6856 ; J3.7 4244,6856 ; v1(5280,7300) 5270,7300 5220,7250 5050,7250 5000,7200 5000,7059.73 4999.2,7058.93 4999.2,6917.47 5000,6916.68 5000,6900 4950,6850 4780.61,6850 4773.61,6857 4557,6857 4482,6782 4318,6782 4244,6856
BIASIN1: J3.6 L3.1 X3.1 | length 1117.3
  Top Layer w12: v1(5000,6780) 5000,6770 5020,6750 X3.1
  Top Layer w20: X3.1 L3.1@5300,6750
  Bottom Layer w12: J3.6 4353,6822 4375,6800 4675,6800 4725,6750 4970,6750 v1(5000,6780)
BIASIN2: J3.10 L9.1 X13.1 | length 1077.8
  Top Layer w12: L9.1@3075,6975 3125,6975 3150,6950 3150,6925 3175,6900 3175,6850 3275,6750 X13.1 3400,6750 3425,6775 3700,6775 3775,6850 3875,6850 3917,6892 J3.10
BIASMON1+: J3.3 R17.2 R19.2 | length 571.2
  Top Layer w12: J3.3 4680,6870 4700,6850 4875,6850 4950,6775 R17.2
  Top Layer w30: R17.2 R19.2
BIASMON1-: J3.15 R21.2 R23.2 | length 475.2
  Top Layer w12: R23.2 v1(4750,6800)
  Top Layer w30: R23.2 R21.2
  Bottom Layer w8: 4734.5,6884.5 J3.15
  Bottom Layer w12: 4734.5,6884.5 4750,6869 v1(4750,6800)
BIASMON2+: J3.5 R41.2 R43.2 | length 1003.2
  Top Layer w12: R43.2 3750,6725 3825,6800 4425,6800 4462,6837 J3.5
  Top Layer w30: R41.2 R43.2
BIASMON2-: J3.17 R45.2 R47.2 | length 1337.8
  Top Layer w12: R45.2 3550,6725 3575,6750 3725,6750 3800,6825 4375,6825 v1(4400,6850)
  Top Layer w30: R47.2 R45.2
  Bottom Layer w8: 4516.5,6891.5 J3.17
  Bottom Layer w12: v1(4400,6850) 4475,6850 4516.5,6891.5
GND: Bolt1.1 Bolt2.1 Bolt3.1 Bolt4.1 C2.2 C4.2 C5.2 C9.2 C10.2 C15.2 C17.2 C18.2 C19.2 C21.1 C22.2 C24.2 C27.2 C28.2 C29.2 C31.2 C33.2 C34.2 C38.2 C39.2 C44.2 C46.2 C47.2 C48.2 C50.1 C51.2 C53.2 C56.2 C57.1 C58.2 D2.2 D3.2 D6.2 D7.1 D10.1 D11.1 D13.2 D14.2 D17.2 D18.1 D19.2 D20.2 J1.2 J2.2 J3.4 J3.16 J3.19 J3.20 J3.23 J3.24 J3.26 J4.3 J4.6 J4.7 J4.8 J4.9 J4.10 L4.1 L10.1 R24.1 R48.1 R53.1 R54.1 RL1.2 RL2.2 U1.2 U1.4 U2.3 U3.3 U4.3 U6.3 U7.2 U7.4 U8.3 U9.3 U10.3 U12.3 U13.5 X10.1 | length 15740.3
  Top Layer w12: v2(2700,5275) 2725,5300 U10.3 ; U9.3 2900,4575 2925,4550 v2(2925,4425) ; C56.2 3425,6000 3400,6025 3400,6100 U12.3 ; C47.2 3850,6100 U8.3 ; C18.2 4400,6100 U2.3 ; C27.2 4875,5975 4850,6000 4850,6100 U6.3 ; v2(5275,4535) 5315,4575 U3.3 ; 5350,5150 5350,5275 5375,5300 U4.3
  Top Layer w15: RL2.2 4165,4690 v1(4200,4725) ; v1(4800,4750) 4815,4735 RL1.2
  Top Layer w30: D17.2 2675,3875 2934.25,3615.75 L10.1 ; v2(2700,6675) 2794.49,6675 2800,6680.51 2930.51,6680.51 2950,6700 D14.2 ; C39.2 v2(3175,5525) ; v1(3175,6650) C34.2 ; C31.2 3290,3510 3300,3500 3519,3500 J2.2@3544,3475 ; v2(3350,5925) 3375,5950 C56.2 ; C48.2 v2(3875,6350) ; v2(3825,5850) 3850,5875 C47.2 ; v2(4200,6350) C33.2 ; v2(4375,5875) 4400,5900 C18.2 ; v2(4725,6350) C4.2 ; v2(4850,5875) 4875,5900 C27.2 ; v1(5150,6400) 5150,6390 5161.49,6378.51 C19.2 ; J3.26@5169,6987.81 5255.62,6901.18 D3.2 5554.33,6901.18 D2.2@5562.5,6893.01 ; v2(5275,4535) D7.1 5280.51,4425 C15.2 ; v1(5275,6050) 5275,5975 C24.2 ; v2(5325,5150) 5350,5150 C17.2 ; L4.1 5453.75,3446.25 5480,3420 5620,3420 5675,3475 D6.2 ; C5.2 D2.2 ; C22.2 5800,6111.43 C21.1 5923.43,6098.43 6000,6175 R24.1 ; C9.2 v2(5925,4725) ; C10.2 5925,5450 v2(5950,5475) ; v1(6000,5775) C58.2 6075,5725 6100,5700 6250,5700 6287.5,5737.5 U13.5 ; C57.1@6200,6275 C57.1 v1(6200,6390)
  Top Layer w40: C53.2 C50.1 ; v2(2700,5275) 2700,5200 C46.2 ; C44.2 v2(2925,4425) ; C51.2 3100,6400 v1(3125,6375) ; R48.1 v1(3225,5950) ; C38.2 v2(3225,4725) ; D18.1 3330.51,4194.49 v2(3400,4125) ; C28.2 3753.5,7171.5 J3.24 ; D20.2 3725,4400 v1(3775,4350) ; D10.1 X10.1 ; J3.20 4189.5,7100 4190,7100 4244,7154 X10.1 ; v1(4250,4450) 4344.49,4450 D19.2 ; J3.16 4625.5,7100.5 4650,7125 4950,7125 4969.49,7144.49 D11.1 ; C29.2 X10.1 ; J1.2@4944,3475 5100,3475 5175,3550 C2.2 ; v1(5970,6640) 6020,6590 R53.1 R54.1
  Dummy Ground w15: J3.26@3319,7069 3319,6987.81 3450.5,7119.31 3450.5,7124.5 4625.5,7124.5 ; J3.4 4571,6989.31 J3.16 4625.5,7124.5 ; J3.26@5169,6987.81 5032.3,7124.5 4625.5,7124.5
  Dummy Ground w30: v1(5150,6400) 5150,6150 5250,6050 v1(5275,6050) 5275,5975 5475,5775 v1(6000,5775) ; C21.1 6048.43,6098.43 6048.43,6238.43 v1(6200,6390)
  Dummy Ground w40: C50.1 2723.43,5950 v1(3225,5950) ; v1(3125,6375) 3075,6425 3075,6550 v1(3175,6650) ; v1(5970,6640) 5970,6620 v1(6200,6390)
NetC1_2: C1.2 U1.1 | length 143
  Top Layer w25: U1.1 C1.2
NetC3_1: C3.1 L1.1 U1.3 | length 303.4
  Top Layer w20: C3.1 C3.1@4850,3750 ; U1.3 C3.1@4850,3750 ; L1.1@4950,3750 C3.1@4850,3750
NetC3_2: C3.2 J1.1 X2.1 | length 513.9
  Top Layer w20: C3.2 4844,3606 J1.1 X2.1
NetC6_1: C6.1 R5.1 R8.2 R11.2 R49.1 U3.2 | length 1430.3
  Top Layer w12: R5.1@5425,4825 R5.1@5575,4825 ; U3.2 5575,4625 ; C6.1 R49.1 R5.1@5575,4825 ; R8.2 R11.2@5980,4275 ; R11.2 R11.2@5980,4275 ; 5575,4625 5600,4600 5600,4400 5725,4275 R11.2@5980,4275 ; 5575,4625 5600,4650 5600,4725 5575,4750 R5.1@5575,4825
NetC6_2: C6.2 R5.2 R9.1 R12.1 R49.2 U3.6 X5.1 | length 1388.2
  Top Layer w12: U3.6 5675,4575 5650,4600 5650,4725 5675,4750 R5.2@5675,4825 ; R5.2@5825,4825 R5.2@5675,4825 ; X5.1 5850,5012 X5.1@5850,5025 ; R12.1 5850,5100 X5.1@5850,5025 ; R9.1 C6.2 ; R5.2@5675,4825 R49.2 C6.2 ; C6.2 X5.1@5850,5025
NetC7_1: C7.1 R50.2 | length 100
  Top Layer w12: R50.2 C7.1
NetC7_2: C7.2 R4.1 R6.2 R13.1 U2.5 U4.6 X4.1 | length 2446.2
  Top Layer w12: R13.1 4350,6000 4325,5975 4325,5775 4350,5750 X4.1 4650,5750 4675,5775 ; U2.5 4700,6037.5 R4.1 4700,5850 4675,5825 4675,5775 ; U4.6 5675,5300 5650,5325 5650,5425 5675,5450 R6.2 C7.2 5675,5675 5625,5725 4775,5725 4725,5775 4675,5775
NetC8_1: C8.1 R3.1 R4.2 U2.6 | length 733.2
  Top Layer w12: R3.1 C8.1 4550,6375 4575,6350 4575,6125 4600,6100 ; R4.2 4600,6100 ; U2.6 4600,6100
NetC8_2: C8.2 R7.1 U2.7 | length 518.6
  Top Layer w12: R7.1 C8.2 4650,6400 4600,6350 4600,6175 4625,6150 U2.7
NetC11_1: C11.1 C14.1 D4.2 D6.1 L2.1 L4.2 R8.1 | length 2636.1
  Top Layer w12: L2.1@5200,4750 v2(5325,4750)
  Top Layer w20: L4.2 5553.75,3641.25 5475,3720 D4.2 5544.49,3855.51 5575,3886.02 5575,4025 5600,4050 D6.1@5680.51,4050 ; D6.1 D6.1@5680.51,4050 ; C11.1 6088.29,3976.29 6088.29,4050 ; C14.1 6088.29,4448.71 6088.29,4050 ; D6.1@5680.51,4050 R8.1 6088.29,4050
  Bottom Layer w12: v2(5325,4750) 5625,4450 C14.1
NetC11_2: C11.2 C14.2 R11.1 | length 968.4
  Top Layer w12: R11.1 5980,4505 6000,4525 6250,4525 6286.43,4488.57 C14.2 C11.2
NetC12_1: C12.1 C16.1 R12.2 | length 811.4
  Top Layer w12: R12.2 6286.43,5225 ; C16.1 6286.43,5225 ; C12.1 6286.43,5225
NetC12_2: C12.2 C16.2 R6.1 R9.2 R50.1 U4.2 | length 1739.1
  Top Layer w12: U4.2 5425,5350 v1(5400,5375) 5400,5475 5425,5500 R50.1 R6.1 ; R9.2 6039.57,4925 C16.2
  Bottom Layer w12: v1(5400,5375) 5425,5400 6000,5400 6050,5450 C12.2 C16.2
NetC13_1: C13.1 R10.1 R13.2 U2.2 | length 651.8
  Top Layer w12: R13.2 U2.2 4525,6150 4550,6175 4550,6275 4450,6375 C13.1 R10.1
NetC13_2: C13.2 R14.1 U2.1 | length 421.6
  Top Layer w12: R14.1 C13.2 4350,6400 4462.5,6287.5 U2.1
NetC20_1: C20.1 R15.1 R16.1 U5.2 | length 440.3
  Top Layer w12: U5.2 5410,6150 5430,6170 5430,6220 5410,6240 5390,6240 5375,6255 R16.1 C20.1 R15.1
NetC20_2: C20.2 R16.2 R18.1 R22.1 U5.6 U6.5 X7.1 | length 1802.2
  Top Layer w12: R22.1 4800,5825 4825,5800 5150,5800 5175,5825 5175,5875 ; U6.5 5137.5,6037.5 5175,6000 R18.1 5175,5875 ; C20.2 R16.2 5475,6165 5540,6100 ; U5.6 5540,6100 ; 5175,5875 5500,5875 5530,5905 5530,6090 5540,6100
NetC21_2: C21.2 R15.2 | length 1125.2
  Top Layer w12: R15.2 5475,6595 v1(5480,6600)
  Bottom Layer w12: v1(5480,6600) 5600,6600 5750,6450 5840,6450 5890,6400 5890,6060 5813,5983 C21.2
NetC23_1: C23.1 R17.1 R18.2 U6.6 | length 739.3
  Top Layer w12: R17.1 C23.1 4950,6325 5025,6250 5025,6150 5075,6100 ; R18.2 5075,6100 ; U6.6 5075,6100
NetC23_2: C23.2 R19.1 U6.7 | length 497.9
  Top Layer w12: R19.1 C23.2 5050,6175 5075,6150 U6.7
NetC25_2: C25.2 R20.1 R24.2 U5.3 | length 1042.3
  Top Layer w12: U5.3@5387.5,6100 v1(5475,6100) ; R20.1 5800,6400 5850,6350 5880,6350 5900,6330 R24.2
  Bottom Layer w12: v1(5475,6100) 5661.43,6100 5813,6251.57 C25.2
NetC26_1: C26.1 R21.1 R22.2 U6.2 | length 672.5
  Top Layer w12: R22.2 U6.2 4975,6150 5000,6175 5000,6225 4925,6300 4925,6400 C26.1 R21.1
NetC26_2: C26.2 R23.1 U6.1 | length 486.2
  Top Layer w12: R23.1 C26.2 4750,6425 4775,6400 4850,6400 4875,6375 4875,6275 4912.5,6237.5 U6.1
NetC28_1: C28.1 D8.2 D10.2 L5.2 | length 519.6
  Top Layer w40: C28.1 3600,7339.02 L5.2 D10.2 3755.51,7294.49 3850,7200 D8.2@3884.45,7200
NetC29_1: C29.1 D9.1 D11.2 L6.2 | length 473.9
  Top Layer w50: D9.1@4615.55,7225 4675,7225 4700,7200 D11.2 4780.51,7319.49 C29.1 L6.2
NetC30_2: C30.2 U7.1 | length 143
  Top Layer w25: U7.1 C30.2
NetC32_1: C32.1 L7.1 U7.3 | length 308
  Top Layer w25: C32.1@3650,3750 U7.3
  Top Layer w30: L7.1@3510,3750 C32.1@3650,3750
NetC32_2: C32.2 J2.1 X12.1 | length 508.5
  Top Layer w25: X12.1 J2.1 3650,3381 C32.2
NetC35_1: C35.1 R29.1 R32.2 R35.2 R51.1 U9.2 | length 912.5
  Top Layer w12: R35.2 2725,4625 ; U9.2 2725,4625 ; C35.1 R51.1 2875,4825 2725,4825 2725,4625
  Top Layer w40: R32.2 R35.2
NetC35_2: C35.2 R29.2 R33.1 R36.1 R51.2 U9.6 X15.1 | length 1410
  Top Layer w12: R36.1 R33.1 2625,5075 2650,5050 ; X15.1 2650,5050 ; U9.6 2975,4575 2950,4600 2950,4725 2975,4750 ; R29.2@3125,4825 3050,4750 2975,4750 ; 2650,5050 2675,5075 2975,5075 C35.2 R51.2 2975,4825 2975,4750
NetC36_1: C36.1 R52.2 | length 100
  Top Layer w12: R52.2 C36.1
NetC36_2: C36.2 R28.1 R30.2 R37.1 U8.5 U10.6 X14.1 | length 2380.3
  Top Layer w12: U10.6 2975,5300 2950,5325 2950,5425 2975,5450 R30.2 C36.2 2975,5675 3025,5725 3675,5725 3775,5825 ; R37.1 3800,5900 3775,5875 3775,5825 ; U8.5 4200,6050 4200,5950 ; R28.1 4200,5950 ; 3775,5825 3800,5800 4000,5800 X14.1 4050,5775 4100,5825 4175,5825 4200,5850 4200,5950
NetC37_1: C37.1 R27.1 R28.2 U8.6 | length 733.2
  Top Layer w12: R28.2 4050,6100 ; R27.1 C37.1 4050,6375 4025,6350 4025,6125 4050,6100 ; U8.6 4050,6100
NetC37_2: C37.2 R31.1 U8.7 | length 539.3
  Top Layer w12: U8.7 4075,6150 4050,6175 4050,6325 4150,6425 C37.2 R31.1
NetC40_1: C40.1 C43.1 D15.2 D17.1 L8.1 L10.2 R32.1 | length 2934.8
  Top Layer w40: C43.1 2201.57,4350 ; C40.1 2201.57,4350 ; R32.1 2550,4350 ; L10.2 3034.25,3690.75 2900,3825 D15.2 2819.49,4005.51 2800,4025 2800,4150 2755.51,4194.49 ; L8.1@3425,4500 3425,4425 3325,4325 2850,4325 2755.51,4230.51 2755.51,4194.49 ; 2201.57,4350 2550,4350 ; 2550,4350 2550,4225 2580.51,4194.49 D17.1 2755.51,4194.49
NetC40_2: C40.2 C43.2 R35.1 | length 771.4
  Top Layer w40: C40.2 2398.43,4573.43 2450,4625 R35.1
  Bottom Layer w40: C43.2 C40.2
NetC41_1: C41.1 C45.1 R36.2 | length 798.4
  Top Layer w12: C45.1 2201.57,5300 ; C41.1 2201.57,5300 ; R36.2 2201.57,5300
NetC41_2: C41.2 C45.2 R30.1 R33.2 R52.1 U10.2 | length 1354.9
  Top Layer w12: C45.2 R33.2 ; C41.2 2550,5450 2650,5350 U10.2 2850,5350 2875,5375 R30.1 R52.1
  Bottom Layer w12: C45.2 C41.2
NetC42_1: C42.1 R34.1 R37.2 U8.2 | length 595.7
  Top Layer w12: R37.2 U8.2 3950,6150 3975,6175 3975,6450 C42.1 R34.1
NetC42_2: C42.2 R38.1 U8.1 | length 425.9
  Top Layer w12: R38.1 C42.2 3850,6425 3875,6400 3900,6400 3925,6375 3925,6212.5 U8.1
NetC49_1: C49.1 R39.1 R40.1 U11.2 | length 991.1
  Top Layer w12: v1(3150,6475) 3150,6425 3175,6400 3225,6400 C49.1@3325,6400
  Top Layer w30: v1(2775,6300) 2750,6275 R39.1 2750,6175 2775,6150 U11.2@2912.5,6150
  Bottom Layer w30: v1(2775,6300) 2950,6475 v1(3150,6475)
NetC49_2: C49.2 R40.2 R42.1 R46.1 U11.6 U12.5 X17.1 | length 1416.9
  Top Layer w12: U11.6 3225,6100 ; R40.2@3225,6300 3325,6300 3325,6200 3250,6200 3225,6175 3225,6100 ; X17.1 3325,5825 3300,5850 3300,6000 3225,6075 3225,6100
  Top Layer w30: X17.1 3450,5825 3500,5775 3625,5775 3725,5875 R42.1 3725,6000 3687.5,6037.5 U12.5
NetC50_2: C50.2 R39.2 | length 136.9
  Top Layer w30: R39.2 2650,6125 2675,6100 C50.2
NetC52_1: C52.1 R41.1 R42.2 U12.6 | length 760
  Top Layer w12: 3625,6100 3575,6150 3575,6325 3650,6400 C52.1 R41.1
  Top Layer w30: R42.2 3625,6000 3600,6025 3600,6075 3625,6100 U12.6
NetC52_2: C52.2 R43.1 U12.7 | length 560
  Top Layer w12: U12.7 3625,6150 3600,6175 3600,6275 3750,6425 C52.2 R43.1
NetC54_2: C54.2 R44.1 R48.2 U11.3 | length 894.7
  Top Layer w12: U11.3@2912.5,6100 2975,6100 ; R44.1 2950,6275 3000,6225 3000,6125 2975,6100 ; R48.2 3025,6050 2975,6100
  Top Layer w30: C54.2 2726.8,6351.57 2787.23,6412.01 2937.01,6412.01 R44.1
NetC55_1: C55.1 R45.1 R46.2 U12.2 | length 656.1
  Top Layer w12: R46.2@3325,6100 3350,6100 3400,6150 U12.2 3525,6150 3550,6175 C55.1
  Top Layer w30: C55.1 R45.1
NetC55_2: C55.2 R47.1 U12.1 | length 380.2
  Top Layer w30: R47.1 C55.2 3450,6375 3462.5,6362.5 U12.1
NetD4_K: D4.1 D5.2 | length 359.7
  Top Layer w40: D5.2 5344.49,3855.51 5375,3886.02 5375,4025 5394.49,4044.49 D4.1
NetD5_K: D5.1 D7.2 | length 186
  Top Layer w40: D5.1 D7.2
NetD15_K: D15.1 D16.2 | length 336.9
  Top Layer w40: D15.1 2955.51,4194.49 3000,4150 3000,4050 3044.49,4005.51 D16.2
NetD16_K: D16.1 D18.2 | length 331.1
  Top Layer w40: D16.1 3105.51,4200 3150,4200 3200,4150 3200,4025 3219.49,4005.51 D18.2
NetL1_2: L1.2 R2.1 | length 125
  Top Layer w20: L1.2@4950,3625 R2.1
NetL7_2: L7.2 R26.1 | length 122.1
  Top Layer w30: R26.1 3505,3630 L7.2@3510,3625
NetR1_1: R1.1 RL1.6 X1.1 | length 520.1
  Top Layer w25: RL1.6 4905,4580 4975,4650 X1.1 4975,4875 R1.1
NetR25_1: R25.1 RL2.6 X11.1 | length 990.4
  Top Layer w25: X11.1 3513,4913 R25.1 ; R25.1@3525,4900 3625,4900 3650,4875 3825,4875 3875,4825 3950,4825 4025,4750 4025,4600 4045,4580 RL2.6
OUT1+: J3.9 R3.2 R7.2 | length 870.3
  Top Layer w12: R3.2 v1(4550,6750)
  Top Layer w30: R3.2 R7.2
  Bottom Layer w12: J3.9 4026,6874 4225,6675 4475,6675 v1(4550,6750)
OUT1-: J3.21 R10.2 R14.2 | length 635.8
  Top Layer w12: R14.2 v1(4350,6725)
  Top Layer w30: R14.2 R10.2
  Bottom Layer w8: 4080.5,6900 J3.21
  Bottom Layer w12: 4080.5,6900 4255.5,6725 v1(4350,6725)
OUT2+: J3.13 R27.2 R31.2 | length 752.4
  Top Layer w12: R27.2 v1(4050,6750)
  Top Layer w30: R27.2 R31.2
  Bottom Layer w12: J3.13 3590,6860 3625,6825 3900,6825 3975,6750 v1(4050,6750)
OUT2-: J3.25 R34.2 R38.2 | length 843.7
  Top Layer w12: R38.2 v1(3850,6750)
  Top Layer w30: R38.2 3900,6675 R34.2
  Bottom Layer w12: J3.25 3568.8,7043.81 3525,7000 3525,6850 3575,6800 3825,6800 3850,6775 v1(3850,6750)
PHOTODIODE1_PIN1: C1.1 D1.2 J4.5 L2.2 R1.2 | length 2293.4
  Top Layer w20: J4.5 4462,5412 4500,5450 4900,5450 4950,5400 4950,5225 4975,5200 5200,5200 5200,4875 5100,4875 5075,4850 5075,4400 C1.1 ; R1.2 D1.2@5050,5184.45
PHOTODIODE1_PIN2: C5.1 C25.1 D1.1 D2.1 D3.1 J4.4 L3.2 R20.2 X6.1 | length 4369.8
  Top Layer w12: 5450,6675 L3.2@5450,6750
  Top Layer w20: J4.4 4353,5403 4450,5500 5000,5500 5050,5450 D1.1@5050,5365.55 ; X6.1 5220,6551.32 5220,6620 v1(5320,6620) 5370,6620 5425,6675 5450,6675 C5.1 5625,6675 ; D3.1 5495.67,7094.49 D2.1 5655.51,7094.49 5672,7078 5672,6722 5625,6675 ; D2.1@5555.51,7050 D2.1@5575,7069.49 ; R20.2 5575,6545 5580,6550 5650,6550 ; C25.1 5811.43,6550 5650,6550 ; 5625,6675 5650,6650 5650,6550
  Bottom Layer w20: J4.4 4353,5528 5220,6395 5220,6540 5300,6620 v1(5320,6620)
PHOTODIODE2_PIN1: C30.1 D12.2 J4.2 L8.2 R25.2 | length 2329.6
  Top Layer w25: C30.1 3550,4575 3500,4625 3425,4625 3425,5184.45 3415.55,5175 3350,5175 3350,5450 3400,5500 4075,5500 4135,5440 J4.2
PHOTODIODE2_PIN2: C34.1 C54.1 D12.1 D13.1 D14.1 J4.1 L9.2 R44.2 X16.1 | length 3602
  Top Layer w25: C54.1 2851.57,6548.43 2875,6525 R44.2 3050,6525 3075,6550 ; D13.1@2800,6869.49 3055.51,6869.49 3075,6850 C34.1 3075,6550 ; v1(3390,6390) 3390,6400 3380,6410 3380,6510 3340,6550 X16.1 3075,6550 ; D12.1@3425,5365.55 3425,5425 3450,5450 3975,5450 4026,5399 J4.1
  Bottom Layer w25: v1(3390,6390) 3405,6390 3625,6170 3625,5950 4026,5549 J4.1
RLY1: D19.1 J3.18 RL1.1 | length 4813.2
  Top Layer w25: D19.1 4384.49,4660 RL1.1 ; RL1.1@4560,4660 4575,4675 v1(4575,4775)
  Bottom Layer w25: J3.18 4407.5,7082.5 4500,7175 5400,7175 5910,6665 5910,6460 5940,6430 5940,5680 5810,5550 5375,5550 4600,4775 v1(4575,4775)
RLY2: D20.1 J3.22 RL2.1 | length 3461.8
  Top Layer w25: v1(3750,4800) 3725,4775 D20.1 3875.51,4669.49 RL2.1
  Bottom Layer w25: v1(3750,4800) 3750,4825 3525,5050 3525,5600 3412.5,5712.5 3412.5,6187.5 3300,6300 3300,6375 3275,6400 3275,6600 3481.3,6806.3 3481.3,7056.3 3575,7150 3943,7150 3971.5,7121.5 J3.22
TEST+: J3.2 R53.2 U13.3 | length 2551.5
  Top Layer w12: J3.2 4844.5,6987.31 4937.31,6987.31 5125,7175 5650,7175 5700,7125 5700,6750 5800,6650 5860,6650 6020,6490 R53.2 6075,6485 6075,6175 5975,6075 5975,5975 6000,5950 U13.3
TEST-: J3.14 R54.2 U13.2 | length 2727.1
  Top Layer w12: J3.14 4943.81,7043.81 5100,7200 5675,7200 5725,7150 5725,6775 5800,6700 6190,6700 6250,6640 6250,6510 6230,6490 R54.2 6160,6470 6160,6430 6125,6395 6125,6125 6150,6100 6150,6025 6125,6000 U13.2
TESTSIG: RL1.5 RL2.5 U13.6 | length 4547.1
  Top Layer w25: RL2.5 3885,4440 3950,4375 4500,4375 4535,4410 v1(4535,4450) RL1.5 ; v1(6200,5600) 6350,5600 6375,5625 6375,5925 6350,5950 U13.6
  Bottom Layer w25: v1(4535,4450) 5050,4450 5175,4325 6150,4325 6200,4375 v1(6200,5600)
pads on no net: J3.1 U3.1 U3.5 U3.8 U4.1 U4.5 U4.8 U5.1 U5.5 U5.8 U9.1 U9.5 U9.8 U10.1 U10.5 U10.8 U11.1 U11.5 U11.8 U13.1 U13.8

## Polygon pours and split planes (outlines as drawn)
GND on Bottom Layer "Top Layer-No Net" (solid, remove dead copper, pour order 0): 2025,3025 6450,3025 6450,7450 2025,7450
GND on Dummy Ground "Top Layer-No Net" (solid, remove dead copper, pour order 2): 2025,7450 6450,7450 6450,3025 2025,3025
-15V on Dummy Power "Top Layer-No Net" (solid, remove dead copper, pour order 4): 2025,7450 6450,7450 6450,3025 2025,3025
+15V on Dummy Power "+15V_L04_P006" (solid, remove dead copper, pour order 6): 2025,7450 6450,7450 6450,3025 2025,3025
GND on Top Layer "Top Layer-GND" (solid, remove dead copper, pour order 8): 2025,3025 6475,3025 6475,7475 2025,7475

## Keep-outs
Keep-Out Layer:
  lines w5: 2750,7210 2750,7330 3120,7330 3120,7210 2750,7210
  lines w10: 2000,3594 ccw(c2594,3594) 2594,3000 5894,3000 ccw(c5894,3594) 6488,3594 6488,6894 ccw(c5894,6894) 5894,7488 2594,7488 ccw(c2594,6894) 2000,6894 2000,3594

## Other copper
Top Layer:
  region: 4434.76,3224.1 4434.76,3221.33 4434.76,3218.56 4434.76,3215.79 4434.76,3213.03 4434.76,3210.26 4434.76,3207.49 4434.76,3204.72 4434.76,3201.96 4434.76,3199.19 4434.76,3196.42 4434.76,3193.65 4434.76,3190.89 4437.53,3190.89 4437.53,3188.12 4467.97,3188.12 4467.97,3185.35 4467.97,3182.58 4465.21,3182.58 4465.21,3179.82 4465.21,3177.05 4462.44,3177.05 4462.44,3174.28 4462.44,3171.51 4459.67,3171.51 4459.67,3168.75 4456.9,3168.75 4456.9,3165.98 4451.37,3165.98 4451.37,3163.21 4426.46,3163.21 4426.46,3165.98 4426.46,3168.75 4426.46,3171.51 4426.46,3174.28 4426.46,3177.05 4426.46,3179.82 4426.46,3182.58 4426.46,3185.35 4426.46,3188.12 4426.46,3190.89 4426.46,3193.65 4426.46,3196.42 4426.46,3199.19 4426.46,3201.96 4426.46,3204.72 4426.46,3207.49 4426.46,3210.26 4426.46,3213.03 4426.46,3215.79 4426.46,3218.56 4426.46,3221.33 4426.46,3224.1 4426.46,3226.86 4434.76,3226.86
  region: 4412.62,3351.4 4420.93,3351.4 4420.93,3348.64 4423.69,3348.64 4423.69,3345.87 4423.69,3343.1 4426.46,3343.1 4426.46,3340.33 4426.46,3337.57 4426.46,3334.8 4426.46,3332.03 4426.46,3329.26 4429.23,3329.26 4429.23,3326.5 4426.46,3326.5 4426.46,3323.73 4426.46,3320.96 4426.46,3318.19 4423.69,3318.19 4423.69,3315.43 4420.93,3315.43 4420.93,3312.66 4418.16,3312.66 4418.16,3309.89 4404.32,3309.89 4404.32,3312.66 4398.79,3312.66 4398.79,3315.43 4396.02,3315.43 4396.02,3318.19 4393.25,3318.19 4393.25,3320.96 4393.25,3323.73 4393.25,3326.5 4390.48,3326.5 4390.48,3329.26 4390.48,3332.03 4390.48,3334.8 4393.25,3334.8 4393.25,3337.57 4393.25,3340.33 4393.25,3343.1 4393.25,3345.87 4396.02,3345.87 4396.02,3348.64 4398.79,3348.64 4398.79,3351.4 4407.09,3351.4 4407.09,3354.17 4412.62,3354.17
  region: 4213.36,3260.07 4218.9,3260.07 4218.9,3257.31 4221.66,3257.31 4221.66,3254.54 4221.66,3251.77 4224.43,3251.77 4224.43,3249 4224.43,3246.24 4224.43,3243.47 4224.43,3240.7 4227.2,3240.7 4227.2,3237.93 4224.43,3237.93 4224.43,3235.17 4224.43,3232.4 4224.43,3229.63 4221.66,3229.63 4221.66,3226.86 4221.66,3224.1 4218.9,3224.1 4218.9,3221.33 4213.36,3221.33 4213.36,3218.56 4207.83,3218.56 4207.83,3215.79 4191.22,3215.79 4191.22,3218.56 4191.22,3221.33 4191.22,3224.1 4191.22,3226.86 4191.22,3229.63 4191.22,3232.4 4191.22,3235.17 4191.22,3237.93 4191.22,3240.7 4191.22,3243.47 4191.22,3246.24 4191.22,3249 4191.22,3251.77 4191.22,3254.54 4191.22,3257.31 4191.22,3260.07 4191.22,3262.84 4213.36,3262.84
  region: 4180.15,3658.6 4185.68,3658.6 4185.68,3655.83 4188.45,3655.83 4188.45,3653.07 4191.22,3653.07 4191.22,3650.3 4191.22,3647.53 4191.22,3644.76 4191.22,3642 4193.99,3642 4193.99,3639.23 4193.99,3636.46 4191.22,3636.46 4191.22,3633.69 4191.22,3630.93 4191.22,3628.16 4188.45,3628.16 4188.45,3625.39 4188.45,3622.62 4185.68,3622.62 4185.68,3619.86 4182.92,3619.86 4182.92,3617.09 4174.61,3617.09 4174.61,3614.32 4158.01,3614.32 4158.01,3617.09 4158.01,3619.86 4158.01,3622.62 4158.01,3625.39 4158.01,3628.16 4158.01,3630.93 4158.01,3633.69 4158.01,3636.46 4158.01,3639.23 4158.01,3642 4158.01,3644.76 4158.01,3647.53 4158.01,3650.3 4158.01,3653.07 4158.01,3655.83 4158.01,3658.6 4158.01,3661.37 4180.15,3661.37
  region: 4462.44,3262.84 4476.28,3262.84 4476.28,3260.07 4481.81,3260.07 4481.81,3257.31 4484.58,3257.31 4484.58,3254.54 4487.35,3254.54 4487.35,3251.77 4490.12,3251.77 4490.12,3249 4492.88,3249 4492.88,3246.24 4492.88,3243.47 4492.88,3240.7 4495.65,3240.7 4495.65,3237.93 4492.88,3237.93 4492.88,3235.17 4495.65,3235.17 4495.65,3232.4 4495.65,3229.63 4495.65,3226.86 4492.88,3226.86 4492.88,3224.1 4495.65,3224.1 4495.65,3221.33 4492.88,3221.33 4492.88,3218.56 4492.88,3215.79 4490.12,3215.79 4490.12,3213.03 4490.12,3210.26 4490.12,3207.49 4487.35,3207.49 4487.35,3204.72 4484.58,3204.72 4484.58,3207.49 4484.58,3210.26 4484.58,3213.03 4481.81,3213.03 4481.81,3215.79 4481.81,3218.56 4479.04,3218.56 4479.04,3221.33 4479.04,3224.1 4476.28,3224.1 4476.28,3226.86 4473.51,3226.86 4473.51,3229.63 4467.97,3229.63 4467.97,3232.4 4462.44,3232.4 4462.44,3235.17 4451.37,3235.17 4451.37,3237.93 4451.37,3240.7 4454.14,3240.7 4454.14,3243.47 4454.14,3246.24 4454.14,3249 4454.14,3251.77 4454.14,3254.54 4454.14,3257.31 4454.14,3260.07 4454.14,3262.84 4459.67,3262.84 4459.67,3265.61 4462.44,3265.61
  region: 4301.92,3260.07 4310.22,3260.07 4310.22,3257.31 4315.76,3257.31 4315.76,3254.54 4321.29,3254.54 4321.29,3251.77 4324.06,3251.77 4324.06,3249 4326.83,3249 4326.83,3246.24 4326.83,3243.47 4329.6,3243.47 4329.6,3240.7 4329.6,3237.93 4332.36,3237.93 4332.36,3235.17 4332.36,3232.4 4332.36,3229.63 4332.36,3226.86 4332.36,3224.1 4335.13,3224.1 4335.13,3221.33 4335.13,3218.56 4332.36,3218.56 4332.36,3215.79 4332.36,3213.03 4332.36,3210.26 4332.36,3207.49 4332.36,3204.72 4329.6,3204.72 4329.6,3201.96 4329.6,3199.19 4326.83,3199.19 4326.83,3196.42 4326.83,3193.65 4324.06,3193.65 4324.06,3190.89 4321.29,3190.89 4321.29,3188.12 4318.53,3188.12 4318.53,3185.35 4312.99,3185.35 4312.99,3182.58 4301.92,3182.58 4301.92,3179.82 4282.55,3179.82 4282.55,3182.58 4282.55,3185.35 4282.55,3188.12 4282.55,3190.89 4279.78,3190.89 4279.78,3193.65 4279.78,3196.42 4279.78,3199.19 4279.78,3201.96 4279.78,3204.72 4279.78,3207.49 4279.78,3210.26 4279.78,3213.03 4279.78,3215.79 4279.78,3218.56 4279.78,3221.33 4279.78,3224.1 4279.78,3226.86 4279.78,3229.63 4279.78,3232.4 4279.78,3235.17 4279.78,3237.93 4279.78,3240.7 4279.78,3243.47 4282.55,3243.47 4282.55,3246.24 4282.55,3249 4282.55,3251.77 4282.55,3254.54 4282.55,3257.31 4282.55,3260.07 4282.55,3262.84 4301.92,3262.84
  region: 4271.48,3658.6 4279.78,3658.6 4279.78,3655.83 4288.08,3655.83 4288.08,3653.07 4290.85,3653.07 4290.85,3650.3 4293.62,3650.3 4293.62,3647.53 4296.39,3647.53 4296.39,3644.76 4296.39,3642 4299.15,3642 4299.15,3639.23 4299.15,3636.46 4301.92,3636.46 4301.92,3633.69 4301.92,3630.93 4301.92,3628.16 4301.92,3625.39 4301.92,3622.62 4304.69,3622.62 4304.69,3619.86 4304.69,3617.09 4301.92,3617.09 4301.92,3614.32 4301.92,3611.55 4301.92,3608.79 4301.92,3606.02 4301.92,3603.25 4299.15,3603.25 4299.15,3600.48 4299.15,3597.72 4299.15,3594.95 4296.39,3594.95 4296.39,3592.18 4293.62,3592.18 4293.62,3589.41 4290.85,3589.41 4290.85,3586.65 4288.08,3586.65 4288.08,3583.88 4282.55,3583.88 4282.55,3581.11 4274.25,3581.11 4274.25,3578.34 4252.11,3578.34 4252.11,3581.11 4252.11,3583.88 4252.11,3586.65 4252.11,3589.41 4252.11,3592.18 4249.34,3592.18 4249.34,3594.95 4249.34,3597.72 4249.34,3600.48 4249.34,3603.25 4249.34,3606.02 4249.34,3608.79 4249.34,3611.55 4249.34,3614.32 4249.34,3617.09 4249.34,3619.86 4249.34,3622.62 4249.34,3625.39 4249.34,3628.16 4249.34,3630.93 4249.34,3633.69 4249.34,3636.46 4249.34,3639.23 4249.34,3642 4252.11,3642 4252.11,3644.76 4252.11,3647.53 4252.11,3650.3 4252.11,3653.07 4252.11,3655.83 4252.11,3658.6 4252.11,3661.37 4271.48,3661.37
  region: 215 vertices and 15 holes, not listed, extent 3920,3110.63 4548.23,3403.99
  region: 215 vertices and 17 holes, not listed, extent 3920,3420.59 4548.23,3713.95
  region: 4088.82,3630.93 4088.82,3628.16 4091.59,3628.16 4091.59,3625.39 4091.59,3622.62 4091.59,3619.86 4094.36,3619.86 4094.36,3617.09 4094.36,3614.32 4097.12,3614.32 4097.12,3611.55 4077.75,3611.55 4077.75,3614.32 4077.75,3617.09 4080.52,3617.09 4080.52,3619.86 4080.52,3622.62 4080.52,3625.39 4083.29,3625.39 4083.29,3628.16 4083.29,3630.93 4086.05,3630.93 4086.05,3633.69 4088.82,3633.69
  region: 4285.32,3511.92 4290.85,3511.92 4290.85,3509.15 4290.85,3506.39 4293.62,3506.39 4293.62,3503.62 4293.62,3500.85 4290.85,3500.85 4290.85,3498.08 4288.08,3498.08 4288.08,3495.32 4282.55,3495.32 4282.55,3492.55 4277.01,3492.55 4277.01,3495.32 4277.01,3498.08 4277.01,3500.85 4277.01,3503.62 4277.01,3506.39 4277.01,3509.15 4277.01,3511.92 4277.01,3514.69 4285.32,3514.69
  region: 4061.15,3351.4 4066.68,3351.4 4066.68,3348.64 4066.68,3345.87 4069.45,3345.87 4069.45,3343.1 4069.45,3340.33 4066.68,3340.33 4066.68,3337.57 4066.68,3334.8 4061.15,3334.8 4061.15,3332.03 4052.84,3332.03 4052.84,3334.8 4052.84,3337.57 4052.84,3340.33 4052.84,3343.1 4052.84,3345.87 4052.84,3348.64 4052.84,3351.4 4052.84,3354.17 4061.15,3354.17
  region: 4003.03,3351.4 4008.56,3351.4 4008.56,3348.64 4011.33,3348.64 4011.33,3345.87 4011.33,3343.1 4011.33,3340.33 4011.33,3337.57 4008.56,3337.57 4008.56,3334.8 4005.79,3334.8 4005.79,3332.03 3994.72,3332.03 3994.72,3334.8 3994.72,3337.57 3994.72,3340.33 3994.72,3343.1 3994.72,3345.87 3994.72,3348.64 3994.72,3351.4 3994.72,3354.17 4003.03,3354.17
  region: 4083.29,3232.4 4083.29,3229.63 4083.29,3226.86 4086.05,3226.86 4086.05,3224.1 4086.05,3221.33 4088.82,3221.33 4088.82,3218.56 4088.82,3215.79 4088.82,3213.03 4069.45,3213.03 4069.45,3215.79 4072.22,3215.79 4072.22,3218.56 4074.98,3218.56 4074.98,3221.33 4074.98,3224.1 4074.98,3226.86 4077.75,3226.86 4077.75,3229.63 4077.75,3232.4 4080.52,3232.4 4080.52,3235.17 4083.29,3235.17
  region: 4454.14,3221.33 4456.9,3221.33 4456.9,3218.56 4459.67,3218.56 4459.67,3215.79 4462.44,3215.79 4462.44,3213.03 4465.21,3213.03 4465.21,3210.26 4465.21,3207.49 4465.21,3204.72 4467.97,3204.72 4467.97,3201.96 4467.97,3199.19 4454.14,3199.19 4454.14,3201.96 4454.14,3204.72 4454.14,3207.49 4454.14,3210.26 4454.14,3213.03 4454.14,3215.79 4454.14,3218.56 4451.37,3218.56 4451.37,3221.33 4451.37,3224.1 4454.14,3224.1
  text "878/5" at 2780,7340 h80
  text "1" at 2780,7230 h80
  text "LIGO D2000592-v2" at 2590,3090 h80
Dummy Ground:
  text "878/5" at 2790,7360 h80
  text "2" at 2850,7230 h80
  text "LIGO D2000592-v2" at 2590,3090 h80
Dummy Power:
  text "878/5" at 2790,7360 h80
  text "3" at 2940,7230 h80
  text "LIGO D2000592-v2" at 2590,3090 h80
Bottom Layer:
  text "878/5" at 3120,7360 h80
  text "4" at 3040,7230 h80
  text "LIGO D2000592-v2" at 3670,3100 h80

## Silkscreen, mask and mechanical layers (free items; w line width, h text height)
Top Overlay:
  lines w10: 3790,5905 3790,6005 ; 5010,3790 5010,3800 5030,3820
  text "LIGO D2000592-v2" at 2590,3090 h80
Bottom Overlay:
  text "LIGO D2000592-v2" at 3670,3100 h80
Mechanical 2:
  lines w10: 2000,3595 2000,3710 ; 2000,3709 2709,3709 2709,3000 ; 2000,6779 2709,6779 2709,7488 ; 2000,6780 2000,6890 ; 2595,3000 2710,3000 ; 2595,7488 2710,7488 ; 5779,3000 5779,3709 6488,3709 ; 5779,7488 5779,6779 6488,6779 ; 5780,3000 5895,3000 ; 5780,7488 5892,7488 ; 6488,3595 6488,3710 ; 6488,6780 6488,6890 ; 3535,4890 3535,5598 4953,5598 4953,4890 3535,4890
Mechanical 4:
  lines w10: 2594,7488 ccw(c2594,6894) 2000,6894 2000,3594 ccw(c2594,3594) 2594,3000 5894,3000 ccw(c5894,3594) 6488,3594 6488,6894 ccw(c5894,6894) 5894,7488 2595,7488
Mechanical 10:
  lines w20: 3500,2950 6475,2950 6550,3025 6550,6175 ; 3520,2950 3180,2950 3150,2980 3150,4140 3285,4275 5375,4275 5575,4475 5575,4550 5550,4575 3100,4575 3050,4625 3050,4825 3075,4850 5600,4850 5650,4900 5650,5475 5600,5525 3550,5525 3300,5275 3100,5275 3075,5300 3075,5725 3100,5750 5600,5750 5675,5825 5675,5950 5625,6000 4075,6000 ; 4125,6000 2925,6000 2825,6100 2825,6425 3000,6600 3475,6600 4400,6600 4400,7525
Mechanical 11:
  lines w10: 2728.35,3019.68 2728.35,7468.5 ; 2728.35,3748.03 5759.84,3748.03 ; 2728.35,6740.16 5759.84,6740.16 ; 5759.84,3019.68 5759.84,7468.5
Mechanical 16:
  lines w10: 3475,4000 3475,3925 3825,3925 3825,4000 ; 3475,4050 3475,4125 3825,4125 3825,4050 ; 4675,4000 4675,3925 5025,3925 5025,4000 ; 4675,4050 4675,4125 5025,4125 5025,4050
